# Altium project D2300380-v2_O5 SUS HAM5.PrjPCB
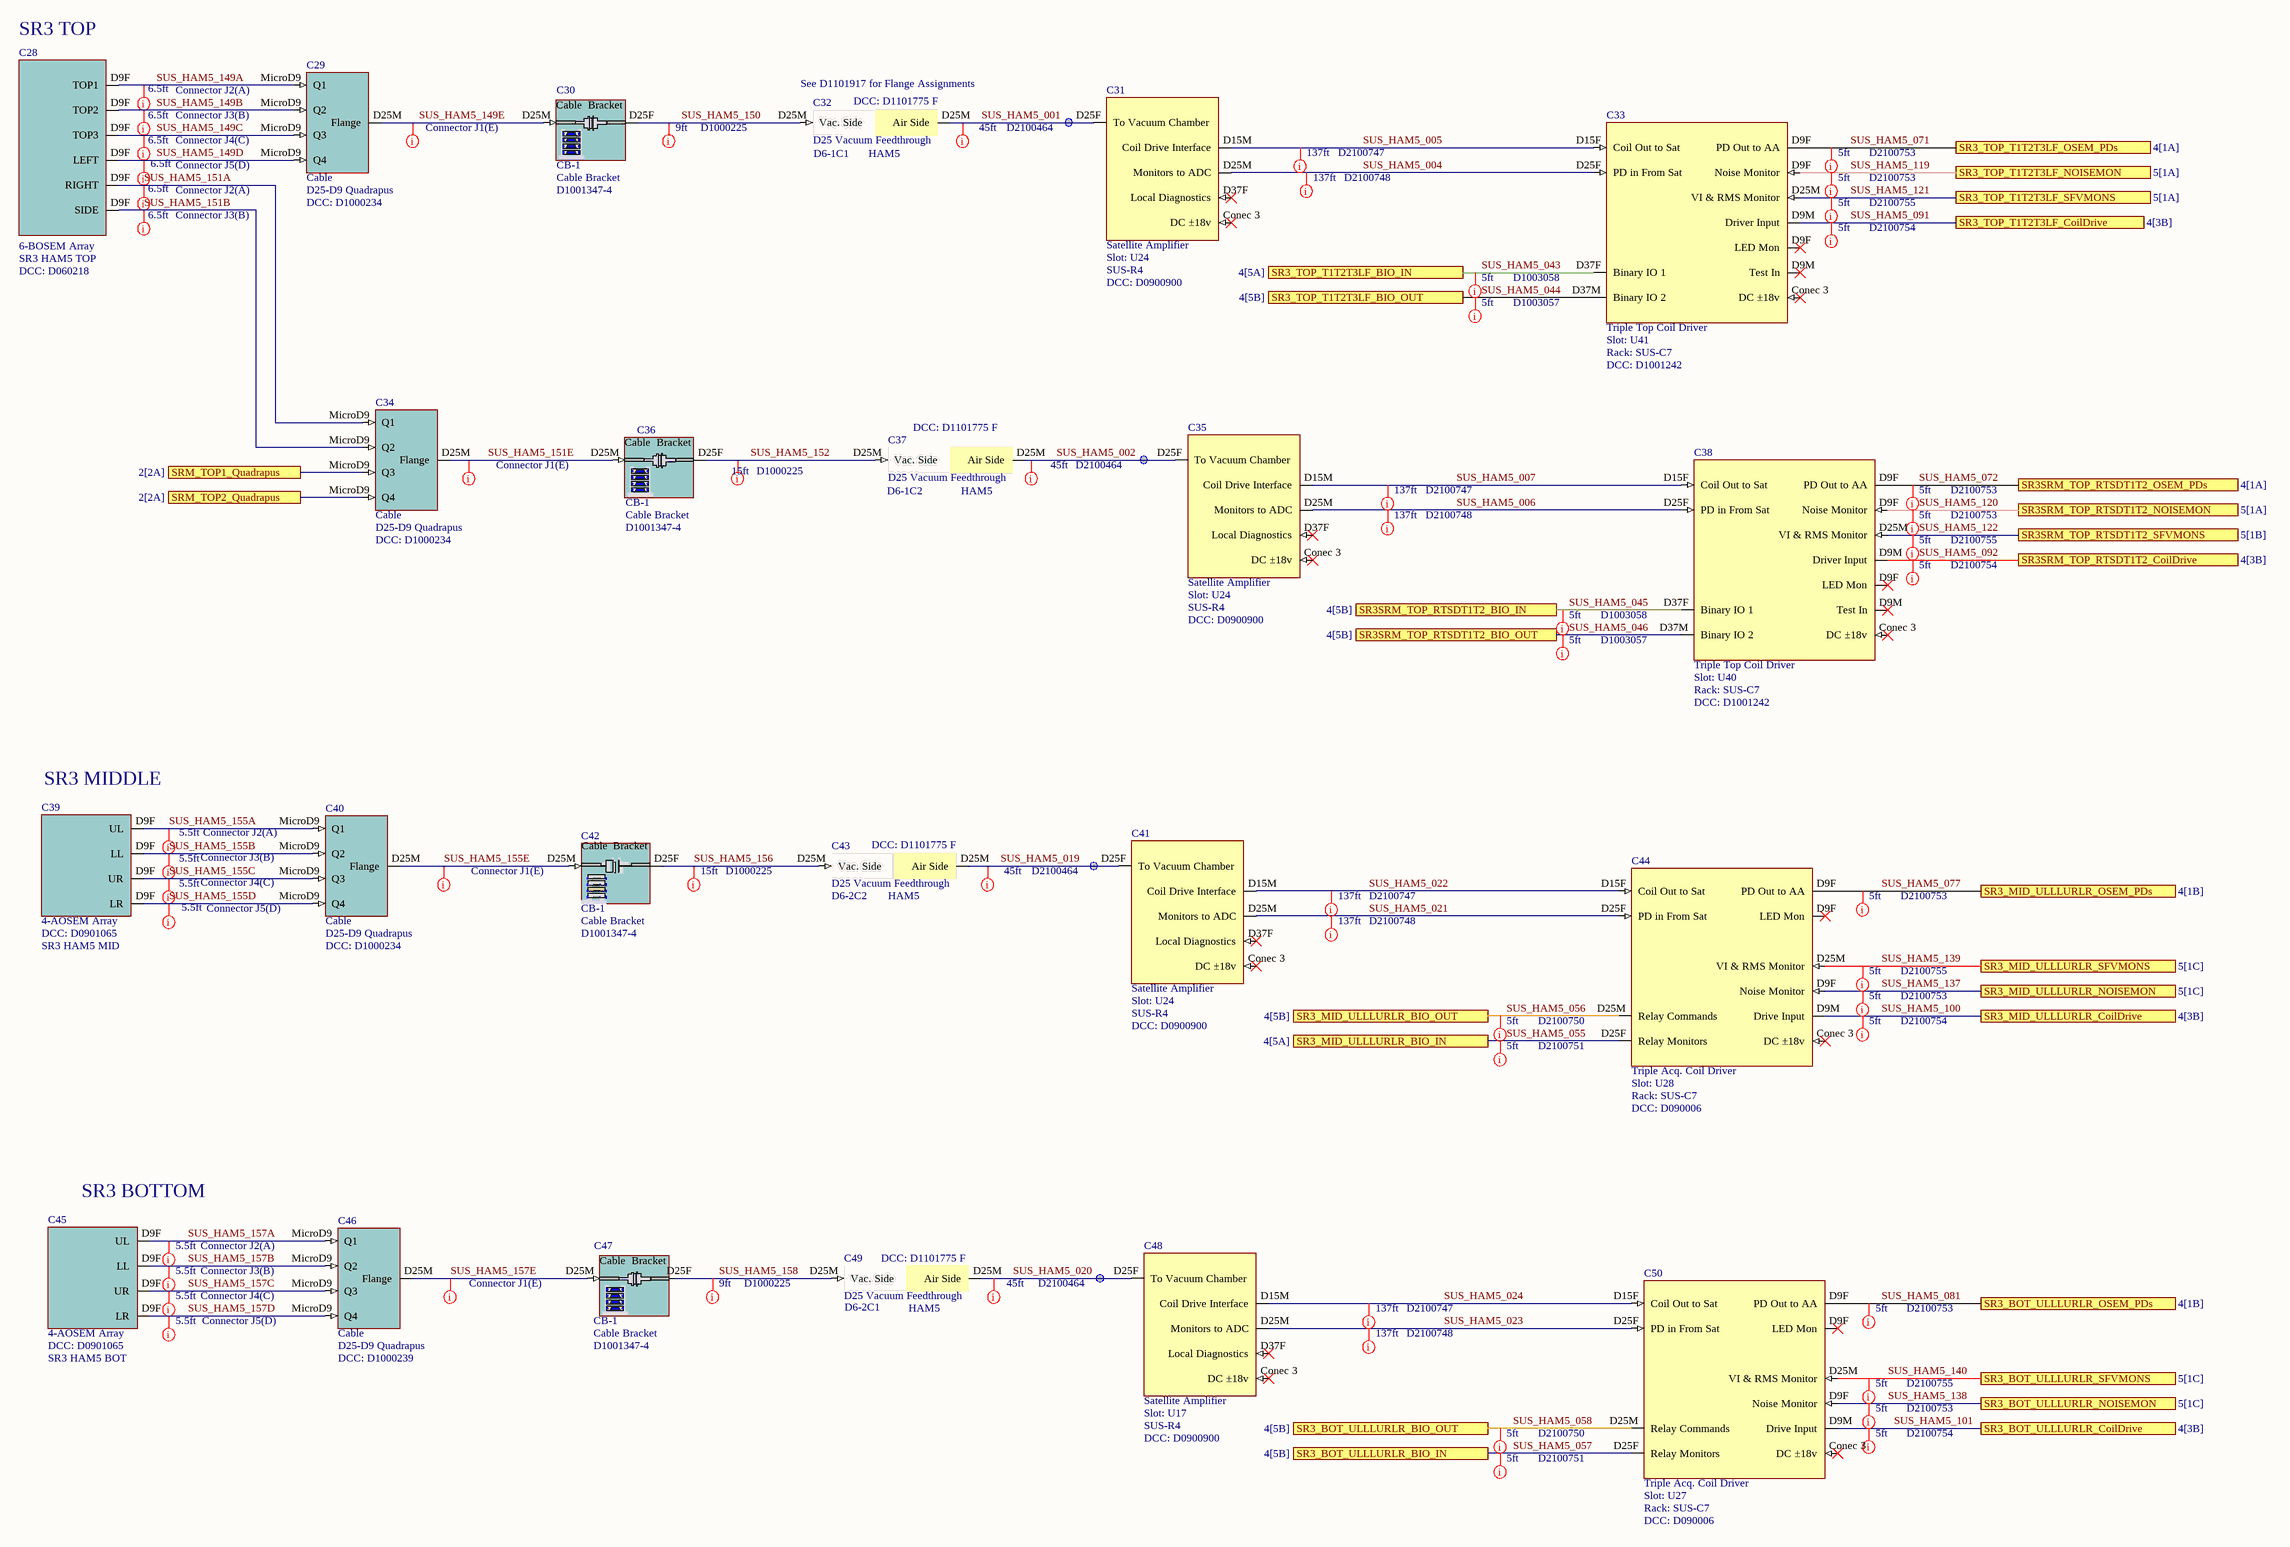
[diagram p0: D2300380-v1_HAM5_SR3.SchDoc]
7 sheets, 104 parts. Net scope: flat (ports and power ports of the same name join across sheets).
Sheets:
  D2300380-v1_HAM5_SR3.SchDoc
  D2300380-v1_HAM5_SRM.SchDoc
  D2300380-v2_HAM5_OFI_ZM6_LO3.SchDoc
  D2300380-v1_SUSH56_ADC_DAC.SchDoc
  D2300380-v1_SUSAUXH56_ADC_DAC.SchDoc
  D2300380-v1_RACK_SUS_R4.SchDoc
  D2300380-v2_RACK_SUS_C7_C8.SchDoc

## Sheet D2300380-v1_HAM5_SR3.SchDoc: HAM5 SR3 OSEMs to Drivers
size C; Engineer: L. Sanchez; Organization: LIGO Laboratory; Address1: California Institute of Technology; Address2: Massachusetts Institute of Technology; DocumentNumber: D2300380; Revision: v1; SheetNumber: 1; SheetTotal: 7

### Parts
C28  6-BOSEM Array  Parameter 1: SR3 HAM5 TOP  DCC: D060218
C29  Cable  value D25-D9 Quadrapus  DCC: D1000234
C30  Slot: CB-1  DCC: D1001347-4  (hidden comment: Cable Bracket)
C31  Satellite Amplifier  Slot: U24  Rack: SUS-R4  DCC: D0900900
C32  D25 Vacuum Feedthrough  DCC: D1101775 F  Feedthrough: D6-1C1  Chamber: HAM5
C33  Triple Top Coil Driver  Slot: U41  Rack: SUS-C7  DCC: D1001242
C34  Cable  value D25-D9 Quadrapus  DCC: D1000234
C35  Satellite Amplifier  Slot: U24  Rack: SUS-R4  DCC: D0900900
C36  Slot: CB-1  DCC: D1001347-4  (hidden comment: Cable Bracket)
C37  D25 Vacuum Feedthrough  DCC: D1101775 F  Feedthrough: D6-1C2  Chamber: HAM5
C38  Triple Top Coil Driver  Slot: U40  Rack: SUS-C7  DCC: D1001242
C39  4-AOSEM Array  DCC: D0901065  Parameter: SR3 HAM5 MID
C40  Cable  value D25-D9 Quadrapus  DCC: D1000234
C41  Satellite Amplifier  Slot: U24  Rack: SUS-R4  DCC: D0900900
C42  Slot: CB-1  DCC: D1001347-4  (hidden comment: Cable Bracket)
C43  D25 Vacuum Feedthrough  DCC: D1101775 F  Feedthrough: D6-2C2  Chamber: HAM5
C44  Triple Acq. Coil Driver  Slot: U28  Rack: SUS-C7  DCC: D090006
C45  4-AOSEM Array  DCC: D0901065  Parameter: SR3 HAM5 BOT
C46  Cable  value D25-D9 Quadrapus  DCC: D1000239
C47  Slot: CB-1  DCC: D1001347-4  (hidden comment: Cable Bracket)
C48  Satellite Amplifier  Slot: U17  Rack: SUS-R4  DCC: D0900900
C49  D25 Vacuum Feedthrough  DCC: D1101775 F  Feedthrough: D6-2C1  Chamber: HAM5
C50  Triple Acq. Coil Driver  Slot: U27  Rack: SUS-C7  DCC: D090006

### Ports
SR3_BOT_ULLLURLR_BIO_IN (see 4[5B]), SR3_BOT_ULLLURLR_BIO_OUT (see 4[5B]), SR3_BOT_ULLLURLR_CoilDrive (see 4[3B]), SR3_BOT_ULLLURLR_NOISEMON (see 5[1C]), SR3_BOT_ULLLURLR_OSEM_PDs (see 4[1B]), SR3_BOT_ULLLURLR_SFVMONS (see 5[1C]), SR3_MID_ULLLURLR_BIO_IN (see 4[5A]), SR3_MID_ULLLURLR_BIO_OUT (see 4[5B]), SR3_MID_ULLLURLR_CoilDrive (see 4[3B]), SR3_MID_ULLLURLR_NOISEMON (see 5[1C]), SR3_MID_ULLLURLR_OSEM_PDs (see 4[1B]), SR3_MID_ULLLURLR_SFVMONS (see 5[1C]), SR3_TOP_T1T2T3LF_BIO_IN (see 4[5A]), SR3_TOP_T1T2T3LF_BIO_OUT (see 4[5B]), SR3_TOP_T1T2T3LF_CoilDrive (see 4[3B]), SR3_TOP_T1T2T3LF_NOISEMON (see 5[1A]), SR3_TOP_T1T2T3LF_OSEM_PDs (see 4[1A]), SR3_TOP_T1T2T3LF_SFVMONS (see 5[1A]), SR3SRM_TOP_RTSDT1T2_BIO_IN (see 4[5B]), SR3SRM_TOP_RTSDT1T2_BIO_OUT (see 4[5B]), SR3SRM_TOP_RTSDT1T2_CoilDrive (see 4[3B]), SR3SRM_TOP_RTSDT1T2_NOISEMON (see 5[1A]), SR3SRM_TOP_RTSDT1T2_OSEM_PDs (see 4[1A]), SR3SRM_TOP_RTSDT1T2_SFVMONS (see 5[1B]), SRM_TOP1_Quadrapus (see 2[2A]), SRM_TOP2_Quadrapus (see 2[2A])

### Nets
SUS_HAM5_001: C31.D25F(To_Vacuum_Chamber) C32.D25M(Air_Side)
SUS_HAM5_002: C35.D25F(To_Vacuum_Chamber) C37.D25M(Air_Side)
SUS_HAM5_004: C31.D25M(Monitors_to_ADC) C33.D25F(PD_in_From_Sat)
SUS_HAM5_005: C31.D15M(Coil_Drive_Interface) C33.D15F(Coil_Out_to_Sat)
SUS_HAM5_006: C35.D25M(Monitors_to_ADC) C38.D25F(PD_in_From_Sat)
SUS_HAM5_007: C35.D15M(Coil_Drive_Interface) C38.D15F(Coil_Out_to_Sat)
SUS_HAM5_019: C41.D25F(To_Vacuum_Chamber) C43.D25M(Air_Side)
SUS_HAM5_020: C48.D25F(To_Vacuum_Chamber) C49.D25M(Air_Side)
SUS_HAM5_021: C41.D25M(Monitors_to_ADC) C44.D25F(PD_in_From_Sat)
SUS_HAM5_022: C41.D15M(Coil_Drive_Interface) C44.D15F(Coil_Out_to_Sat)
SUS_HAM5_023: C48.D25M(Monitors_to_ADC) C50.D25F(PD_in_From_Sat)
SUS_HAM5_024: C48.D15M(Coil_Drive_Interface) C50.D15F(Coil_Out_to_Sat)
SUS_HAM5_043: C33.D37F(Binary_IO_1) ; port SR3_TOP_T1T2T3LF_BIO_IN
SUS_HAM5_044: C33.D37M(Binary_IO_2) ; port SR3_TOP_T1T2T3LF_BIO_OUT
SUS_HAM5_045: C38.D37F(Binary_IO_1) ; port SR3SRM_TOP_RTSDT1T2_BIO_IN
SUS_HAM5_046: C38.D37M(Binary_IO_2) ; port SR3SRM_TOP_RTSDT1T2_BIO_OUT
SUS_HAM5_055: C44.D25F(Relay_Monitors) ; port SR3_MID_ULLLURLR_BIO_IN
SUS_HAM5_056: C44.D25M(Relay_Commands) ; port SR3_MID_ULLLURLR_BIO_OUT
SUS_HAM5_057: C50.D25F(Relay_Monitors) ; port SR3_BOT_ULLLURLR_BIO_IN
SUS_HAM5_058: C50.D25M(Relay_Commands) ; port SR3_BOT_ULLLURLR_BIO_OUT
SUS_HAM5_071: C33.D9F(PD_Out_to_AA) ; port SR3_TOP_T1T2T3LF_OSEM_PDs
SUS_HAM5_072: C38.D9F(PD_Out_to_AA) ; port SR3SRM_TOP_RTSDT1T2_OSEM_PDs
SUS_HAM5_077: C44.D9F(PD_Out_to_AA) ; port SR3_MID_ULLLURLR_OSEM_PDs
SUS_HAM5_081: C50.D9F(PD_Out_to_AA) ; port SR3_BOT_ULLLURLR_OSEM_PDs
SUS_HAM5_091: C33.D9M(Test_In) ; port SR3_TOP_T1T2T3LF_CoilDrive
SUS_HAM5_092: C38.D9M(Test_In) ; port SR3SRM_TOP_RTSDT1T2_CoilDrive
SUS_HAM5_100: C44.D9M(Drive_Input) ; port SR3_MID_ULLLURLR_CoilDrive
SUS_HAM5_101: C50.D9M(Drive_Input) ; port SR3_BOT_ULLLURLR_CoilDrive
SUS_HAM5_119: C33.D9F(Noise_Monitor) ; port SR3_TOP_T1T2T3LF_NOISEMON
SUS_HAM5_120: C38.D9F(Noise_Monitor) ; port SR3SRM_TOP_RTSDT1T2_NOISEMON
SUS_HAM5_121: C33.D25M(VI_&_RMS_Monitor) ; port SR3_TOP_T1T2T3LF_SFVMONS
SUS_HAM5_122: C38.D25M(VI_&_RMS_Monitor) ; port SR3SRM_TOP_RTSDT1T2_SFVMONS
SUS_HAM5_137: C44.D9F(Noise_Monitor) ; port SR3_MID_ULLLURLR_NOISEMON
SUS_HAM5_138: C50.D9F(Noise_Monitor) ; port SR3_BOT_ULLLURLR_NOISEMON
SUS_HAM5_139: C44.D25M(VI_&_RMS_Monitor) ; port SR3_MID_ULLLURLR_SFVMONS
SUS_HAM5_140: C50.D25M(VI_&_RMS_Monitor) ; port SR3_BOT_ULLLURLR_SFVMONS
SUS_HAM5_149A: C28.D9F(TOP1) C29.MicroD9(Q1)
SUS_HAM5_149B: C28.D9F(TOP2) C29.MicroD9(Q2)
SUS_HAM5_149C: C28.D9F(TOP3) C29.MicroD9(Q3)
SUS_HAM5_149D: C28.D9F(LEFT) C29.MicroD9(Q4)
SUS_HAM5_149E: C29.D25M(Flange) C30.D25M
SUS_HAM5_150: C30.D25F C32.D25M(Vac._Side)
SUS_HAM5_151A: C28.D9F(RIGHT) C34.MicroD9(Q1)
SUS_HAM5_151B: C28.D9F(SIDE) C34.MicroD9(Q2)
SUS_HAM5_151C: C34.MicroD9(Q3) ; port SRM_TOP1_Quadrapus
SUS_HAM5_151D: C34.MicroD9(Q4) ; port SRM_TOP2_Quadrapus
SUS_HAM5_151E: C34.D25M(Flange) C36.D25M
SUS_HAM5_152: C36.D25F C37.D25M(Vac._Side)
SUS_HAM5_155A: C39.D9F(UL) C40.MicroD9(Q1)
SUS_HAM5_155B: C39.D9F(LL) C40.MicroD9(Q2)
SUS_HAM5_155C: C39.D9F(UR) C40.MicroD9(Q3)
SUS_HAM5_155D: C39.D9F(LR) C40.MicroD9(Q4)
SUS_HAM5_155E: C40.D25M(Flange) C42.D25M
SUS_HAM5_156: C42.D25F C43.D25M(Vac._Side)
SUS_HAM5_157A: C45.D9F(UL) C46.MicroD9(Q1)
SUS_HAM5_157B: C45.D9F(LL) C46.MicroD9(Q2)
SUS_HAM5_157C: C45.D9F(UR) C46.MicroD9(Q3)
SUS_HAM5_157D: C45.D9F(LR) C46.MicroD9(Q4)
SUS_HAM5_157E: C46.D25M(Flange) C47.D25M
SUS_HAM5_158: C47.D25F C49.D25M(Vac._Side)

Not connected (* = marked no-connect by the designer): C31 Conec 3(DC_±18v)* D37F(Local_Diagnostics)*; C33 Conec 3(DC_±18v)*; C35 Conec 3(DC_±18v)* D37F(Local_Diagnostics)*; C38 Conec 3(DC_±18v)*; C41 Conec 3(DC_±18v)* D37F(Local_Diagnostics)*; C44 Conec 3(DC_±18v)*; C48 Conec 3(DC_±18v)* D37F(Local_Diagnostics)*; C50 Conec 3(DC_±18v)*

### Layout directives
Length: 6.5ft; DCC: Connector J1(E): SUS_HAM5_149E, SUS_HAM5_151E
Length: 15ft; DCC: D1000225: SUS_HAM5_152, SUS_HAM5_156
Length: 45ft; DCC: D2100464: SUS_HAM5_001, SUS_HAM5_002, SUS_HAM5_019, SUS_HAM5_020
Length: 6.5ft; DCC: Connector J2(A): SUS_HAM5_149A, SUS_HAM5_151A
Length: 6.5ft; DCC: Connector J3(B): SUS_HAM5_149B, SUS_HAM5_151B
Length: 9ft; DCC: D1000225: SUS_HAM5_150, SUS_HAM5_158
Length: 6.5ft; DCC: Connector J4(C): SUS_HAM5_149C
Length: 6.5ft; DCC: Connector J5(D): SUS_HAM5_149D
Length: 5ft; DCC: Connector J1(E): SUS_HAM5_157E
Length: 5.5ft; DCC: Connector J1(E): SUS_HAM5_155E
Length: 5.5ft; DCC: Connector J2(A): SUS_HAM5_155A, SUS_HAM5_157A
Length: 5.5ft; DCC: Connector J3(B): SUS_HAM5_155B, SUS_HAM5_157B
Length: 5.5ft; DCC: Connector J4(C): SUS_HAM5_155C, SUS_HAM5_157C
Length: 5.5ft; DCC: Connector J5(D): SUS_HAM5_155D, SUS_HAM5_157D
Length: 137ft; DCC: D2100748: SUS_HAM5_004, SUS_HAM5_006, SUS_HAM5_021, SUS_HAM5_023
Length: 137ft; DCC: D2100747: SUS_HAM5_005, SUS_HAM5_007, SUS_HAM5_022, SUS_HAM5_024
Length: 5ft; DCC: D1003058: SUS_HAM5_043, SUS_HAM5_045
Length: 5ft; DCC: D1003057: SUS_HAM5_044, SUS_HAM5_046
Length: 5ft; DCC: D2100754: SUS_HAM5_091, SUS_HAM5_092, SUS_HAM5_100, SUS_HAM5_101
Length: 5ft; DCC: D2100755: SUS_HAM5_121, SUS_HAM5_122, SUS_HAM5_139, SUS_HAM5_140
Length: 5ft; DCC: D2100753: SUS_HAM5_071, SUS_HAM5_072, SUS_HAM5_077, SUS_HAM5_081, SUS_HAM5_119, SUS_HAM5_120, SUS_HAM5_137, SUS_HAM5_138
Length: 5ft; DCC: D2100751: SUS_HAM5_055, SUS_HAM5_057
Length: 5ft; DCC: D2100750: SUS_HAM5_056, SUS_HAM5_058

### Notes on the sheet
- (near C28) SR3 TOP
- (near C32) See D1101917 for Flange Assignments
- (near C39) SR3 MIDDLE
- (near C45) SR3 BOTTOM

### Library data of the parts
C28 = 6-BOSEM Array HAM: Serial: Sxxxxxxx; System: SUS; Slot: U?; Rack: SUS-R?
C29 C34 C40 C46 = Flange: Rack: SUS-R?; Serial: Sxxxxxxx; Slot: U?; System: SUS
C30 = Cable Bracket 3 1-4: Rack: SUS-R?; Serial: Sxxxxxxx; System: SUS
C31 C35 C41 C48 = Satellite Amplifier: System: SUS; Serial: Sxxxxxxx
C32 C37 C43 C49 = VacFeedD25: Serial: Sxxxxxxx; System: ISC; Rack: R?; Slot: U?
C33 C38 = Triple Top CD: System: SUS; Serial: Sxxxxxxx
C36 = Cable Bracket 4 1-4: Rack: SUS-R?; Serial: Sxxxxxxx; System: SUS
C39 C45 = 4-BOSEM Array: Rack: SUS-R?; Serial: Sxxxxxxx; Slot: U?; System: SUS
C42 = Cable Bracket 2 1-4: Rack: SUS-R?; Serial: Sxxxxxxx; System: SUS
C44 C50 = Triple Acquisition Coil Driver: System: SUS; Serial: Sxxxxxxx
C47 = Cable Bracket 1 1-4: Rack: SUS-R?; Serial: Sxxxxxxx; System: SUS

## Sheet D2300380-v1_HAM5_SRM.SchDoc: HAM5 SRM OSEMs to Drivers
size C; Engineer: L. Sanchez; Organization: LIGO Laboratory; Address1: California Institute of Technology; Address2: Massachusetts Institute of Technology; DocumentNumber: D2300380; Revision: v1; SheetNumber: 2; SheetTotal: 7
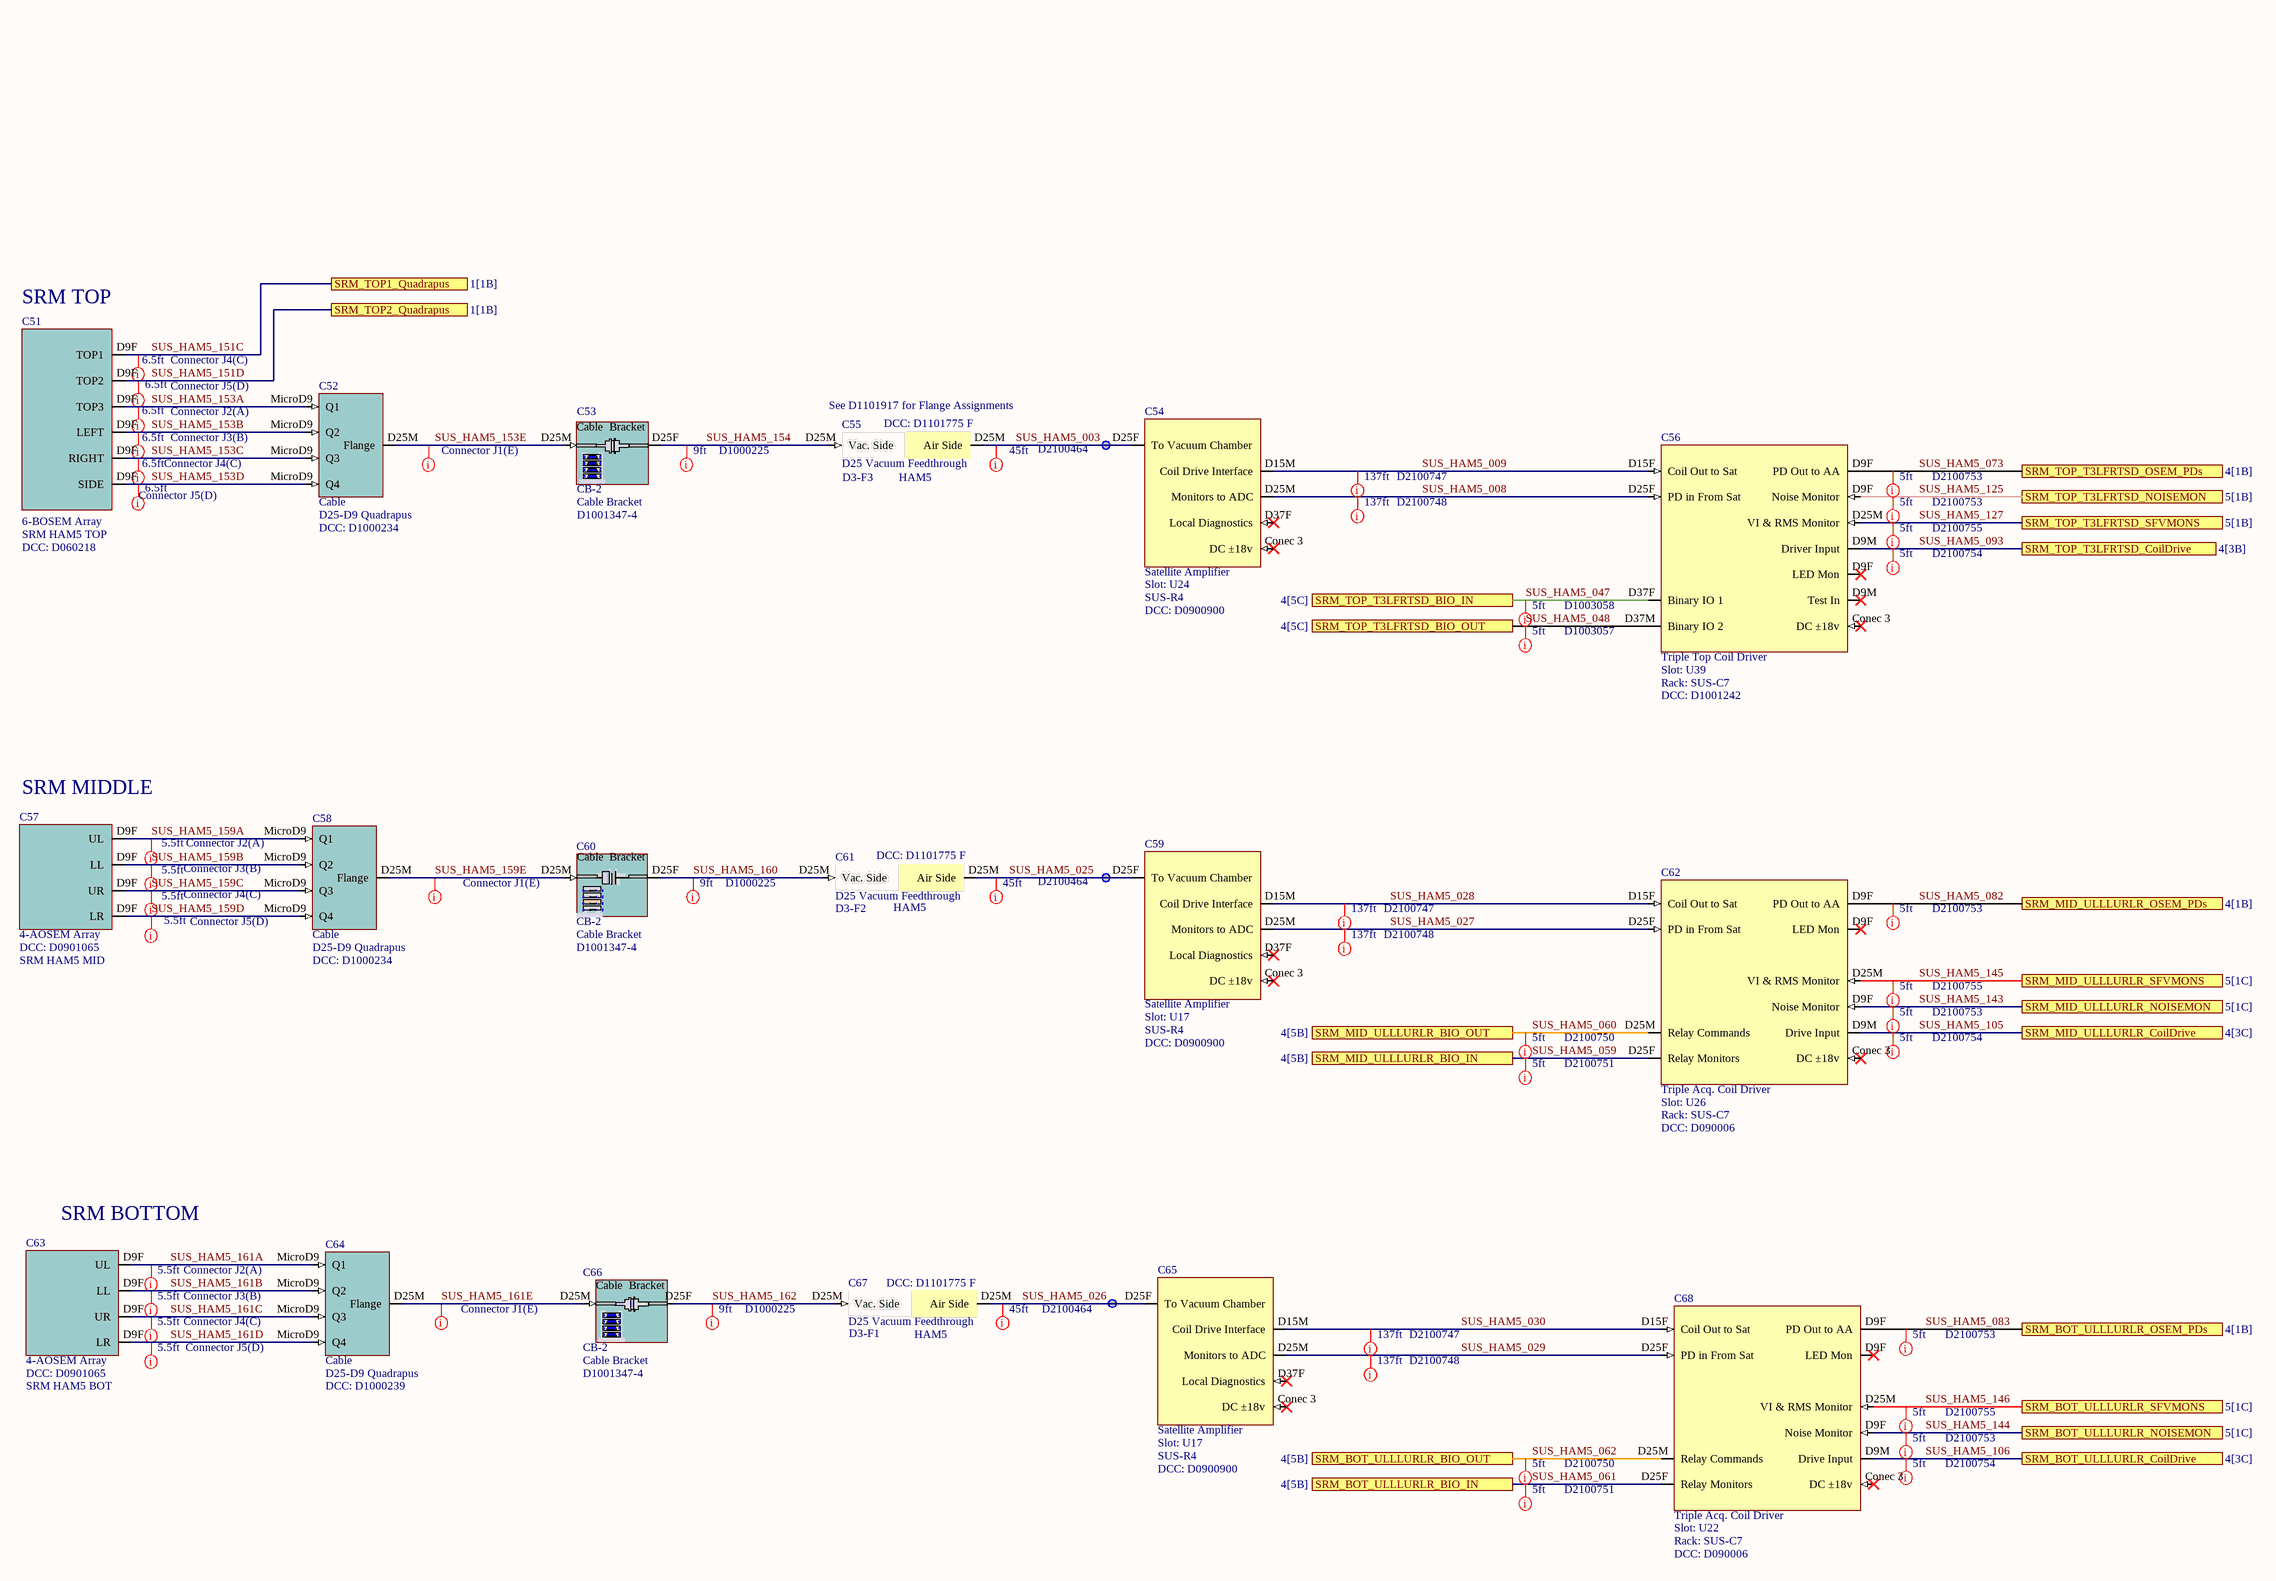
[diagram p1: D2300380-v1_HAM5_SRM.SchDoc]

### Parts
C51  6-BOSEM Array  Parameter 1: SRM HAM5 TOP  DCC: D060218
C52  Cable  value D25-D9 Quadrapus  DCC: D1000234
C53  Slot: CB-2  DCC: D1001347-4  (hidden comment: Cable Bracket)
C54  Satellite Amplifier  Slot: U24  Rack: SUS-R4  DCC: D0900900
C55  D25 Vacuum Feedthrough  DCC: D1101775 F  Feedthrough: D3-F3  Chamber: HAM5
C56  Triple Top Coil Driver  Slot: U39  Rack: SUS-C7  DCC: D1001242
C57  4-AOSEM Array  DCC: D0901065  Parameter: SRM HAM5 MID
C58  Cable  value D25-D9 Quadrapus  DCC: D1000234
C59  Satellite Amplifier  Slot: U17  Rack: SUS-R4  DCC: D0900900
C60  Slot: CB-2  DCC: D1001347-4  (hidden comment: Cable Bracket)
C61  D25 Vacuum Feedthrough  DCC: D1101775 F  Feedthrough: D3-F2  Chamber: HAM5
C62  Triple Acq. Coil Driver  Slot: U26  Rack: SUS-C7  DCC: D090006
C63  4-AOSEM Array  DCC: D0901065  Parameter: SRM HAM5 BOT
C64  Cable  value D25-D9 Quadrapus  DCC: D1000239
C65  Satellite Amplifier  Slot: U17  Rack: SUS-R4  DCC: D0900900
C66  Slot: CB-2  DCC: D1001347-4  (hidden comment: Cable Bracket)
C67  D25 Vacuum Feedthrough  DCC: D1101775 F  Feedthrough: D3-F1  Chamber: HAM5
C68  Triple Acq. Coil Driver  Slot: U22  Rack: SUS-C7  DCC: D090006

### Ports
SRM_BOT_ULLLURLR_BIO_IN (see 4[5B]), SRM_BOT_ULLLURLR_BIO_OUT (see 4[5B]), SRM_BOT_ULLLURLR_CoilDrive (see 4[3C]), SRM_BOT_ULLLURLR_NOISEMON (see 5[1C]), SRM_BOT_ULLLURLR_OSEM_PDs (see 4[1B]), SRM_BOT_ULLLURLR_SFVMONS (see 5[1C]), SRM_MID_ULLLURLR_BIO_IN (see 4[5B]), SRM_MID_ULLLURLR_BIO_OUT (see 4[5B]), SRM_MID_ULLLURLR_CoilDrive (see 4[3C]), SRM_MID_ULLLURLR_NOISEMON (see 5[1C]), SRM_MID_ULLLURLR_OSEM_PDs (see 4[1B]), SRM_MID_ULLLURLR_SFVMONS (see 5[1C]), SRM_TOP1_Quadrapus (see 1[1B]), SRM_TOP2_Quadrapus (see 1[1B]), SRM_TOP_T3LFRTSD_BIO_IN (see 4[5C]), SRM_TOP_T3LFRTSD_BIO_OUT (see 4[5C]), SRM_TOP_T3LFRTSD_CoilDrive (see 4[3B]), SRM_TOP_T3LFRTSD_NOISEMON (see 5[1B]), SRM_TOP_T3LFRTSD_OSEM_PDs (see 4[1B]), SRM_TOP_T3LFRTSD_SFVMONS (see 5[1B])

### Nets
SUS_HAM5_003: C54.D25F(To_Vacuum_Chamber) C55.D25M(Air_Side)
SUS_HAM5_008: C54.D25M(Monitors_to_ADC) C56.D25F(PD_in_From_Sat)
SUS_HAM5_009: C54.D15M(Coil_Drive_Interface) C56.D15F(Coil_Out_to_Sat)
SUS_HAM5_025: C59.D25F(To_Vacuum_Chamber) C61.D25M(Air_Side)
SUS_HAM5_026: C65.D25F(To_Vacuum_Chamber) C67.D25M(Air_Side)
SUS_HAM5_027: C59.D25M(Monitors_to_ADC) C62.D25F(PD_in_From_Sat)
SUS_HAM5_028: C59.D15M(Coil_Drive_Interface) C62.D15F(Coil_Out_to_Sat)
SUS_HAM5_029: C65.D25M(Monitors_to_ADC) C68.D25F(PD_in_From_Sat)
SUS_HAM5_030: C65.D15M(Coil_Drive_Interface) C68.D15F(Coil_Out_to_Sat)
SUS_HAM5_047: C56.D37F(Binary_IO_1) ; port SRM_TOP_T3LFRTSD_BIO_IN
SUS_HAM5_048: C56.D37M(Binary_IO_2) ; port SRM_TOP_T3LFRTSD_BIO_OUT
SUS_HAM5_059: C62.D25F(Relay_Monitors) ; port SRM_MID_ULLLURLR_BIO_IN
SUS_HAM5_060: C62.D25M(Relay_Commands) ; port SRM_MID_ULLLURLR_BIO_OUT
SUS_HAM5_061: C68.D25F(Relay_Monitors) ; port SRM_BOT_ULLLURLR_BIO_IN
SUS_HAM5_062: C68.D25M(Relay_Commands) ; port SRM_BOT_ULLLURLR_BIO_OUT
SUS_HAM5_073: C56.D9F(PD_Out_to_AA) ; port SRM_TOP_T3LFRTSD_OSEM_PDs
SUS_HAM5_082: C62.D9F(PD_Out_to_AA) ; port SRM_MID_ULLLURLR_OSEM_PDs
SUS_HAM5_083: C68.D9F(PD_Out_to_AA) ; port SRM_BOT_ULLLURLR_OSEM_PDs
SUS_HAM5_093: C56.D9M(Test_In) ; port SRM_TOP_T3LFRTSD_CoilDrive
SUS_HAM5_105: C62.D9M(Drive_Input) ; port SRM_MID_ULLLURLR_CoilDrive
SUS_HAM5_106: C68.D9M(Drive_Input) ; port SRM_BOT_ULLLURLR_CoilDrive
SUS_HAM5_125: C56.D9F(Noise_Monitor) ; port SRM_TOP_T3LFRTSD_NOISEMON
SUS_HAM5_127: C56.D25M(VI_&_RMS_Monitor) ; port SRM_TOP_T3LFRTSD_SFVMONS
SUS_HAM5_143: C62.D9F(Noise_Monitor) ; port SRM_MID_ULLLURLR_NOISEMON
SUS_HAM5_144: C68.D9F(Noise_Monitor) ; port SRM_BOT_ULLLURLR_NOISEMON
SUS_HAM5_145: C62.D25M(VI_&_RMS_Monitor) ; port SRM_MID_ULLLURLR_SFVMONS
SUS_HAM5_146: C68.D25M(VI_&_RMS_Monitor) ; port SRM_BOT_ULLLURLR_SFVMONS
SUS_HAM5_151C: C51.D9F(TOP1) ; port SRM_TOP1_Quadrapus
SUS_HAM5_151D: C51.D9F(TOP2) ; port SRM_TOP2_Quadrapus
SUS_HAM5_153A: C51.D9F(TOP3) C52.MicroD9(Q1)
SUS_HAM5_153B: C51.D9F(LEFT) C52.MicroD9(Q2)
SUS_HAM5_153C: C51.D9F(RIGHT) C52.MicroD9(Q3)
SUS_HAM5_153D: C51.D9F(SIDE) C52.MicroD9(Q4)
SUS_HAM5_153E: C52.D25M(Flange) C53.D25M
SUS_HAM5_154: C53.D25F C55.D25M(Vac._Side)
SUS_HAM5_159A: C57.D9F(UL) C58.MicroD9(Q1)
SUS_HAM5_159B: C57.D9F(LL) C58.MicroD9(Q2)
SUS_HAM5_159C: C57.D9F(UR) C58.MicroD9(Q3)
SUS_HAM5_159D: C57.D9F(LR) C58.MicroD9(Q4)
SUS_HAM5_159E: C58.D25M(Flange) C60.D25M
SUS_HAM5_160: C60.D25F C61.D25M(Vac._Side)
SUS_HAM5_161A: C63.D9F(UL) C64.MicroD9(Q1)
SUS_HAM5_161B: C63.D9F(LL) C64.MicroD9(Q2)
SUS_HAM5_161C: C63.D9F(UR) C64.MicroD9(Q3)
SUS_HAM5_161D: C63.D9F(LR) C64.MicroD9(Q4)
SUS_HAM5_161E: C64.D25M(Flange) C66.D25M
SUS_HAM5_162: C66.D25F C67.D25M(Vac._Side)

Not connected (* = marked no-connect by the designer): C54 Conec 3(DC_±18v)* D37F(Local_Diagnostics)*; C56 Conec 3(DC_±18v)*; C59 Conec 3(DC_±18v)* D37F(Local_Diagnostics)*; C62 Conec 3(DC_±18v)*; C65 Conec 3(DC_±18v)* D37F(Local_Diagnostics)*; C68 Conec 3(DC_±18v)*

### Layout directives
Length: 5ft; DCC: Connector J1(E): SUS_HAM5_161E
Length: 5.5ft; DCC: Connector J1(E): SUS_HAM5_159E
Length: 6.5ft; DCC: Connector J1(E): SUS_HAM5_153E
Length: 6.5ft; DCC: Connector J2(A): SUS_HAM5_153A
Length: 6.5ft; DCC: Connector J3(B): SUS_HAM5_153B
Length: 6.5ft; DCC: Connector J4(C): SUS_HAM5_151C, SUS_HAM5_153C
Length: 6.5ft; DCC: Connector J5(D): SUS_HAM5_151D, SUS_HAM5_153D
Length: 5.5ft; DCC: Connector J2(A): SUS_HAM5_159A, SUS_HAM5_161A
Length: 5.5ft; DCC: Connector J3(B): SUS_HAM5_159B, SUS_HAM5_161B
Length: 5.5ft; DCC: Connector J4(C): SUS_HAM5_159C, SUS_HAM5_161C
Length: 5.5ft; DCC: Connector J5(D): SUS_HAM5_159D, SUS_HAM5_161D
Length: 9ft; DCC: D1000225: SUS_HAM5_154, SUS_HAM5_160, SUS_HAM5_162
Length: 45ft; DCC: D2100464: SUS_HAM5_003, SUS_HAM5_025, SUS_HAM5_026
Length: 137ft; DCC: D2100748: SUS_HAM5_008, SUS_HAM5_027, SUS_HAM5_029
Length: 137ft; DCC: D2100747: SUS_HAM5_009, SUS_HAM5_028, SUS_HAM5_030
Length: 5ft; DCC: D1003057: SUS_HAM5_048
Length: 5ft; DCC: D1003058: SUS_HAM5_047
Length: 5ft; DCC: D2100751: SUS_HAM5_059, SUS_HAM5_061
Length: 5ft; DCC: D2100750: SUS_HAM5_060, SUS_HAM5_062
Length: 5ft; DCC: D2100754: SUS_HAM5_093, SUS_HAM5_105, SUS_HAM5_106
Length: 5ft; DCC: D2100755: SUS_HAM5_127, SUS_HAM5_145, SUS_HAM5_146
Length: 5ft; DCC: D2100753: SUS_HAM5_073, SUS_HAM5_082, SUS_HAM5_083, SUS_HAM5_125, SUS_HAM5_143, SUS_HAM5_144

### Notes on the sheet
- (near C51) SRM TOP
- (near C55) See D1101917 for Flange Assignments
- (near C57) SRM MIDDLE
- (near C63) SRM BOTTOM

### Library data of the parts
C51 = 6-BOSEM Array HAM: as C28 on sheet D2300380-v1_HAM5_SR3
C52 C58 C64 = Flange: as C29 on sheet D2300380-v1_HAM5_SR3
C53 = Cable Bracket 3 1-4: as C30 on sheet D2300380-v1_HAM5_SR3
C54 C59 C65 = Satellite Amplifier: System: SUS; Serial: Sxxxxxxx
C55 C61 C67 = VacFeedD25: as C32 on sheet D2300380-v1_HAM5_SR3
C56 = Triple Top CD: System: SUS; Serial: Sxxxxxxx
C57 C63 = 4-BOSEM Array: as C39 on sheet D2300380-v1_HAM5_SR3
C60 = Cable Bracket 2 1-4: as C42 on sheet D2300380-v1_HAM5_SR3
C62 C68 = Triple Acquisition Coil Driver: System: SUS; Serial: Sxxxxxxx
C66 = Cable Bracket 1 1-4: as C47 on sheet D2300380-v1_HAM5_SR3

## Sheet D2300380-v2_HAM5_OFI_ZM6_LO3.SchDoc: HAM5 OFI, ZM6, LO3 OSEMs to Drivers
size C; Engineer: L. Sanchez; Organization: LIGO Laboratory; Address1: California Institute of Technology; Address2: Massachusetts Institute of Technology; DocumentNumber: D2300380; Revision: v1; SheetNumber: 3; SheetTotal: 7
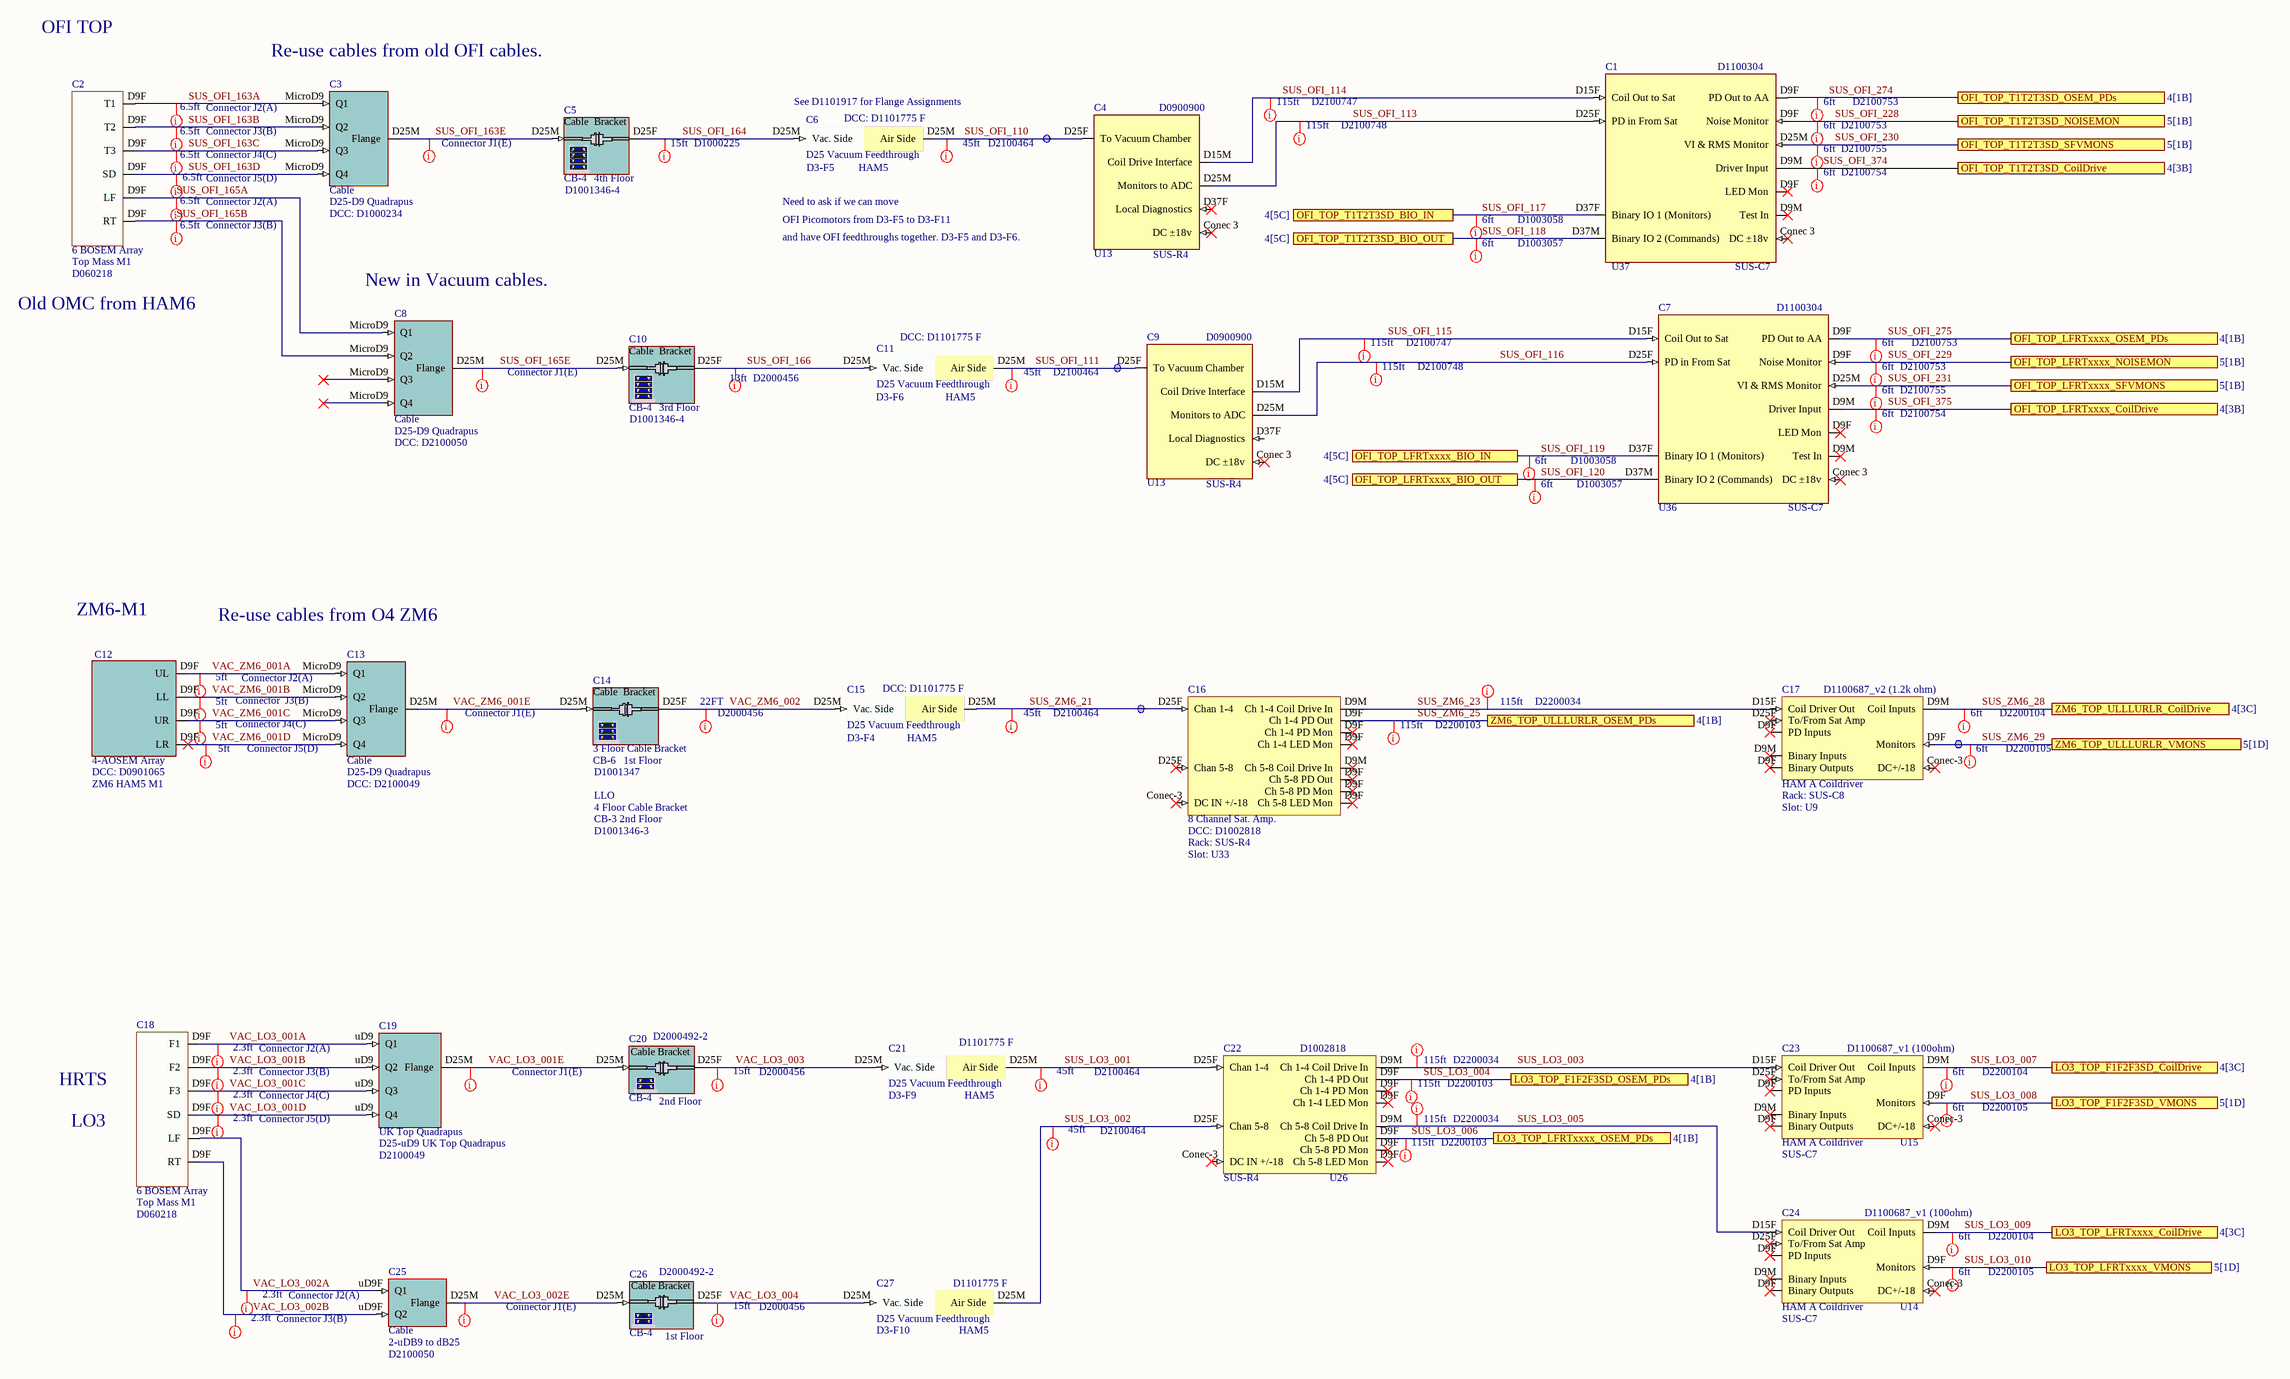
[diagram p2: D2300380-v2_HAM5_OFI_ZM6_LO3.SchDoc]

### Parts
C1  Slot: U37  Rack: SUS-C7  DCC: D1100304  (hidden comment: CD OMC TCD D1100304)
C2  6 BOSEM Array  Parameter: Top Mass M1  DCC: D060218
C3  Cable  value D25-D9 Quadrapus  DCC: D1000234
C4  Slot: U13  Rack: SUS-R4  DCC: D0900900  (hidden comment: Satellite Amplifier UK D0900900)
C5  Rack: CB-4  Slot: 4th Floor  DCC: D1001346-4  (hidden comment: D1001346-4 4th Cable Bracket)
C6  D25 Vacuum Feedthrough  DCC: D1101775 F  Feedthrough: D3-F5  Chamber: HAM5
C7  Slot: U36  Rack: SUS-C7  DCC: D1100304  (hidden comment: CD OMC TCD D1100304)
C8  Cable  value D25-D9 Quadrapus  DCC: D2100050
C9  Slot: U13  Rack: SUS-R4  DCC: D0900900  (hidden comment: Satellite Amplifier UK D0900900)
C10  Rack: CB-4  Slot: 3rd Floor  DCC: D1001346-4  (hidden comment: D1001346-4 3rd Cable Bracket)
C11  D25 Vacuum Feedthrough  DCC: D1101775 F  Feedthrough: D3-F6  Chamber: HAM5
C12  4-AOSEM Array  DCC: D0901065  Parameter: ZM6 HAM5 M1
C13  Cable  value D25-D9 Quadrapus  DCC: D2100049
C14  3 Floor Cable Bracket  Rack: CB-6  Slot: 1st Floor  DCC: D1001347
C15  D25 Vacuum Feedthrough  DCC: D1101775 F  Feedthrough: D3-F4  Chamber: HAM5
C16  8 Channel Sat. Amp.  DCC: D1002818  Rack: SUS-R4  Slot: U33
C17  HAM A Coildriver  DCC: D1100687_v2 (1.2k ohm)  Rack: SUS-C8  Slot: U9
C18  6 BOSEM Array  Parameter: Top Mass M1  DCC: D060218
C19  UK Top Quadrapus  Parameter: D25-uD9 UK Top Quadrapus  DCC: D2100049
C20  Rack: CB-4  Slot: 2nd Floor  DCC: D2000492-2  (hidden comment: Cable Bracket)
C21  D25 Vacuum Feedthrough  value D3-F9  DCC: D1101775 F  Chamber: HAM5
C22  DCC: D1002818  Rack: SUS-R4  Slot: U26  (hidden comment: Satellite Amplifier US D1002818 Dual)
C23  HAM A Coildriver  DCC: D1100687_v1 (100ohm)  Rack: SUS-C7  Slot: U15
C24  HAM A Coildriver  DCC: D1100687_v1 (100ohm)  Rack: SUS-C7  Slot: U14
C25  Cable  value 2-uDB9 to dB25  DCC: D2100050
C26  Rack: CB-4  Slot: 1st Floor  DCC: D2000492-2  (hidden comment: Cable Bracket)
C27  D25 Vacuum Feedthrough  value D3-F10  DCC: D1101775 F  Chamber: HAM5

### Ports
LO3_TOP_F1F2F3SD_CoilDrive (see 4[3C]), LO3_TOP_F1F2F3SD_OSEM_PDs (see 4[1B]), LO3_TOP_F1F2F3SD_VMONS (see 5[1D]), LO3_TOP_LFRTxxxx_CoilDrive (see 4[3C]), LO3_TOP_LFRTxxxx_OSEM_PDs (see 4[1B]), LO3_TOP_LFRTxxxx_VMONS (see 5[1D]), OFI_TOP_LFRTxxxx_BIO_IN (see 4[5C]), OFI_TOP_LFRTxxxx_BIO_OUT (see 4[5C]), OFI_TOP_LFRTxxxx_CoilDrive (see 4[3B]), OFI_TOP_LFRTxxxx_NOISEMON (see 5[1B]), OFI_TOP_LFRTxxxx_OSEM_PDs (see 4[1B]), OFI_TOP_LFRTxxxx_SFVMONS (see 5[1B]), OFI_TOP_T1T2T3SD_BIO_IN (see 4[5C]), OFI_TOP_T1T2T3SD_BIO_OUT (see 4[5C]), OFI_TOP_T1T2T3SD_CoilDrive (see 4[3B]), OFI_TOP_T1T2T3SD_NOISEMON (see 5[1B]), OFI_TOP_T1T2T3SD_OSEM_PDs (see 4[1B]), OFI_TOP_T1T2T3SD_SFVMONS (see 5[1B]), ZM6_TOP_ULLLURLR_CoilDrive (see 4[3C]), ZM6_TOP_ULLLURLR_OSEM_PDs (see 4[1B]), ZM6_TOP_ULLLURLR_VMONS (see 5[1D])

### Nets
SUS_LO3_001: C21.D25M(Air_Side) C22.D25F(Chan_1-4)
SUS_LO3_002: C22.D25F(Chan_5-8) C27.D25M(Air_Side)
SUS_LO3_003: C22.D9M(Ch_1-4_Coil_Drive_In) C23.D15F(Coil_Driver_Out)
SUS_LO3_004: C22.D9F(Ch_1-4_PD_Out) ; port LO3_TOP_F1F2F3SD_OSEM_PDs
SUS_LO3_005: C22.D9M(Ch_5-8_Coil_Drive_In) C24.D15F(Coil_Driver_Out)
SUS_LO3_006: C22.D9F(Ch_5-8_PD_Out) ; port LO3_TOP_LFRTxxxx_OSEM_PDs
SUS_LO3_007: C23.D9M(Coil_Inputs) ; port LO3_TOP_F1F2F3SD_CoilDrive
SUS_LO3_008: C23.D9F(PD_Inputs) ; port LO3_TOP_F1F2F3SD_VMONS
SUS_LO3_009: C24.D9M(Coil_Inputs) ; port LO3_TOP_LFRTxxxx_CoilDrive
SUS_LO3_010: C24.D9F(PD_Inputs) ; port LO3_TOP_LFRTxxxx_VMONS
SUS_OFI_110: C4.D25F(To_Vacuum_Chamber) C6.D25M(Air_Side)
SUS_OFI_111: C9.D25F(To_Vacuum_Chamber) C11.D25M(Air_Side)
SUS_OFI_113: C1.D25F(PD_in_From_Sat) C4.D25M(Monitors_to_ADC)
SUS_OFI_114: C1.D15F(Coil_Out_to_Sat) C4.D15M(Coil_Drive_Interface)
SUS_OFI_115: C7.D15F(Coil_Out_to_Sat) C9.D15M(Coil_Drive_Interface)
SUS_OFI_116: C7.D25F(PD_in_From_Sat) C9.D25M(Monitors_to_ADC)
SUS_OFI_117: C1.D37F(Binary_IO_1_(Monitors)) ; port OFI_TOP_T1T2T3SD_BIO_IN
SUS_OFI_118: C1.D37M(Binary_IO_2_(Commands)) ; port OFI_TOP_T1T2T3SD_BIO_OUT
SUS_OFI_119: C7.D37F(Binary_IO_1_(Monitors)) ; port OFI_TOP_LFRTxxxx_BIO_IN
SUS_OFI_120: C7.D37M(Binary_IO_2_(Commands)) ; port OFI_TOP_LFRTxxxx_BIO_OUT
SUS_OFI_163A: C2.D9F(T1) C3.MicroD9(Q1)
SUS_OFI_163B: C2.D9F(T2) C3.MicroD9(Q2)
SUS_OFI_163C: C2.D9F(T3) C3.MicroD9(Q3)
SUS_OFI_163D: C2.D9F(SD) C3.MicroD9(Q4)
SUS_OFI_163E: C3.D25M(Flange) C5.D25M
SUS_OFI_164: C5.D25F C6.D25M(Vac._Side)
SUS_OFI_165A: C2.D9F(LF) C8.MicroD9(Q1)
SUS_OFI_165B: C2.D9F(RT) C8.MicroD9(Q2)
SUS_OFI_165E: C8.D25M(Flange) C10.D25M
SUS_OFI_166: C10.D25F C11.D25M(Vac._Side)
SUS_OFI_228: C1.D9F(Noise_Monitor) ; port OFI_TOP_T1T2T3SD_NOISEMON
SUS_OFI_229: C7.D9F(Noise_Monitor) ; port OFI_TOP_LFRTxxxx_NOISEMON
SUS_OFI_230: C1.D25M(VI_&_RMS_Monitor) ; port OFI_TOP_T1T2T3SD_SFVMONS
SUS_OFI_231: C7.D25M(VI_&_RMS_Monitor) ; port OFI_TOP_LFRTxxxx_SFVMONS
SUS_OFI_274: C1.D9F(PD_Out_to_AA) ; port OFI_TOP_T1T2T3SD_OSEM_PDs
SUS_OFI_275: C7.D9F(PD_Out_to_AA) ; port OFI_TOP_LFRTxxxx_OSEM_PDs
SUS_OFI_374: C1.D9M(Test_In) ; port OFI_TOP_T1T2T3SD_CoilDrive
SUS_OFI_375: C7.D9M(Test_In) ; port OFI_TOP_LFRTxxxx_CoilDrive
SUS_ZM6_21: C15.D25M(Air_Side) C16.D25F(Chan_1-4)
SUS_ZM6_23: C16.D9M(Ch_1-4_Coil_Drive_In) C17.D15F(Coil_Driver_Out)
SUS_ZM6_25: C16.D9F(Ch_1-4_PD_Out) ; port ZM6_TOP_ULLLURLR_OSEM_PDs
SUS_ZM6_28: C17.D9M(Coil_Inputs) ; port ZM6_TOP_ULLLURLR_CoilDrive
SUS_ZM6_29: C17.D9F(PD_Inputs) ; port ZM6_TOP_ULLLURLR_VMONS
VAC_LO3_001A: C18.D9F(F1) C19.uD9(Q1)
VAC_LO3_001B: C18.D9F(F2) C19.uD9(Q2)
VAC_LO3_001C: C18.D9F(F3) C19.uD9(Q3)
VAC_LO3_001D: C18.D9F(SD) C19.uD9(Q4)
VAC_LO3_001E: C19.D25M(Flange) C20.D25M
VAC_LO3_002A: C18.D9F(LF) C25.uD9F(Q1)
VAC_LO3_002B: C18.D9F(RT) C25.uD9F(Q2)
VAC_LO3_002E: C25.D25M(Flange) C26.D25M
VAC_LO3_003: C20.D25F C21.D25M(Vac._Side)
VAC_LO3_004: C26.D25F C27.D25M(Vac._Side)
VAC_ZM6_001A: C12.D9F(UL) C13.MicroD9(Q1)
VAC_ZM6_001B: C12.D9F(LL) C13.MicroD9(Q2)
VAC_ZM6_001C: C12.D9F(UR) C13.MicroD9(Q3)
VAC_ZM6_001D: C12.D9F(LR) C13.MicroD9(Q4)
VAC_ZM6_001E: C13.D25M(Flange) C14.D25M
VAC_ZM6_002: C14.D25F C15.D25M(Vac._Side)

Not connected (* = marked no-connect by the designer): C1 Conec 3(DC_±18v)*; C4 Conec 3(DC_±18v)* D37F(Local_Diagnostics)*; C7 Conec 3(DC_±18v)*; C9 Conec 3(DC_±18v)* D37F(Local_Diagnostics); C16 Conec-3(DC_IN_+/-18)*; C17 Conec-3(DC+/-18)* D25F(To/From_Sat_Amp)*; C22 Conec-3(DC_IN_+/-18)*; C23 Conec-3(DC+/-18)* D25F(To/From_Sat_Amp)*; C24 Conec-3(DC+/-18)* D25F(To/From_Sat_Amp)*

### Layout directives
Length: 5ft; DCC: Connector J5(D): VAC_ZM6_001D
Length: 5ft; DCC: Connector J2(A): VAC_ZM6_001A
Length: 5ft; DCC: Connector  J3(B): VAC_ZM6_001B
Length: 5ft; DCC: Connector J4(C): VAC_ZM6_001C
Length: 115ft; DCC: D2200034: SUS_LO3_003, SUS_LO3_005, SUS_ZM6_23
Length: 115ft; DCC: D2200103: SUS_LO3_004, SUS_LO3_006, SUS_ZM6_25
Length: 6ft; DCC: D2200105: SUS_LO3_008, SUS_LO3_010, SUS_ZM6_29
Length: 6ft; DCC: D2200104: SUS_LO3_007, SUS_LO3_009, SUS_ZM6_28
Length: 2.3ft; DCC: Connector J2(A): VAC_LO3_001A, VAC_LO3_002A
Length: 2.3ft; DCC: Connector J3(B): VAC_LO3_001B, VAC_LO3_002B
Length: 2.3ft; DCC: Connector J4(C): VAC_LO3_001C
Length: 2.3ft; DCC: Connector J5(D): VAC_LO3_001D
Length: 2.3ft; DCC: Connector J1(E): VAC_LO3_001E, VAC_LO3_002E
Length: 15ft; DCC: D2000456: VAC_LO3_003, VAC_LO3_004
Length: 6.5ft; DCC: Connector J1(E): SUS_OFI_163E, SUS_OFI_165E
Length: 13ft; DCC: D2000456: SUS_OFI_166
Length: 45ft; DCC: D2100464: SUS_LO3_001, SUS_LO3_002, SUS_OFI_110, SUS_OFI_111, SUS_ZM6_21
Length: 6.5ft; DCC: Connector J2(A): SUS_OFI_163A, SUS_OFI_165A
Length: 6.5ft; DCC: Connector J3(B): SUS_OFI_163B, SUS_OFI_165B
Length: 15ft; DCC: D1000225: SUS_OFI_164
Length: 6.5ft; DCC: Connector J4(C): SUS_OFI_163C
Length: 6.5ft; DCC: Connector J5(D): SUS_OFI_163D
Length: 115ft; DCC: D2100747: SUS_OFI_114, SUS_OFI_115
Length: 115ft; DCC: D2100748: SUS_OFI_113, SUS_OFI_116
Length: 6ft; DCC: D2100754: SUS_OFI_374, SUS_OFI_375
Length: 6ft; DCC: D2100753: SUS_OFI_228, SUS_OFI_229, SUS_OFI_274, SUS_OFI_275
Length: 6ft; DCC: D2100755: SUS_OFI_230, SUS_OFI_231
Length: 6ft; DCC: D1003058: SUS_OFI_117, SUS_OFI_119
Length: 6ft; DCC: D1003057: SUS_OFI_118, SUS_OFI_120
Length: 5ft; DCC: Connector J1(E): VAC_ZM6_001E
Length: 22FT; DCC: D2000456: VAC_ZM6_002

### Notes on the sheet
- OFI TOP
- (near C3) Re-use cables from old OFI cables.
- (near C6) See D1101917 for Flange Assignments
- OFI Picomotors from D3-F5 to D3-F11
- Need to ask if we can move
- (near C8) New in Vacuum cables.
- (near C4) and have OFI feedthroughs together. D3-F5 and D3-F6.
- Old OMC from HAM6
- ZM6-M1
- Re-use cables from O4 ZM6
- LLO
- 4 Floor Cable Bracket
- CB-3 2nd Floor
- D1001346-3
- HRTS
- LO3

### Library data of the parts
C1 C7 = CD OMC D1100304: System: SUS; Serial: Sxxxxxxx
C2 = BOSEM_OFI_M1: BOSEM; Serial: Sxxxxxxx; System: SUS; Rack: R?; Slot: U?
C3 C8 C13 = Flange: as C29 on sheet D2300380-v1_HAM5_SR3
C4 C9 = Satellite Amplifier UK D0900900: System: SUS; Serial: Sxxxxxxx
C5 = D1001346-4 4th Cable Bracket: Serial: Sxxxxxxx; System: SUS
C6 C11 C15 C21 C27 = VacFeedD25: as C32 on sheet D2300380-v1_HAM5_SR3
C10 = D1001346-4 3rd Cable Bracket: Serial: Sxxxxxxx; System: SUS
C12 = 4-BOSEM Array: as C39 on sheet D2300380-v1_HAM5_SR3
C14 = 3 Floor Cable Bracket 1st: Cable Bracket; Serial: Sxxxxxxx; System: SUS
C16 = 8 Channel Sat. Amp.: Serial: Sxxxxxxx; System: ISC
C17 = HAM A Coildriver: Serial: Sxxxxxxx; System: ISC
C18 = BOSEM_BS_M1: BOSEM; Serial: Sxxxxxxx; System: SUS; Rack: R?; Slot: U?
C19 = D1000234 D25 Quadrapus: Slot: U?; Rack: R?; Serial: Sxxxxxxx; System: SUS
C20 = D2000492-2 2nd Cable Bracket: D2000492-2 2/2 Cable Bracket for BSC Tables; Serial: Sxxxxxxx; System: SUS
C22 = Satellite Amplifier US D1002818: Serial: Sxxxxxxx
C23 C24 = CD HAM-A D1100687: Serial: Sxxxxxxx; System: ISC
C25 = D2100050 D25 2-udB9: Rack: SUS-R?; Serial: Sxxxxxxx; Slot: U?; System: SUS
C26 = D2000492-2 1st Cable Bracket: D2000492-2 1/2 Cable Bracket for BSC Tables; Serial: Sxxxxxxx; System: SUS

## Sheet D2300380-v1_SUSH56_ADC_DAC.SchDoc: SUS HAM5 Controls IO Chains
size C; Engineer: L. Sanchez; Organization: LIGO Laboratory; Address1: California Institute of Technology; Address2: Massachusetts Institute of Technology; DocumentNumber: D2300380; Revision: v1; SheetNumber: 4; SheetTotal: 7
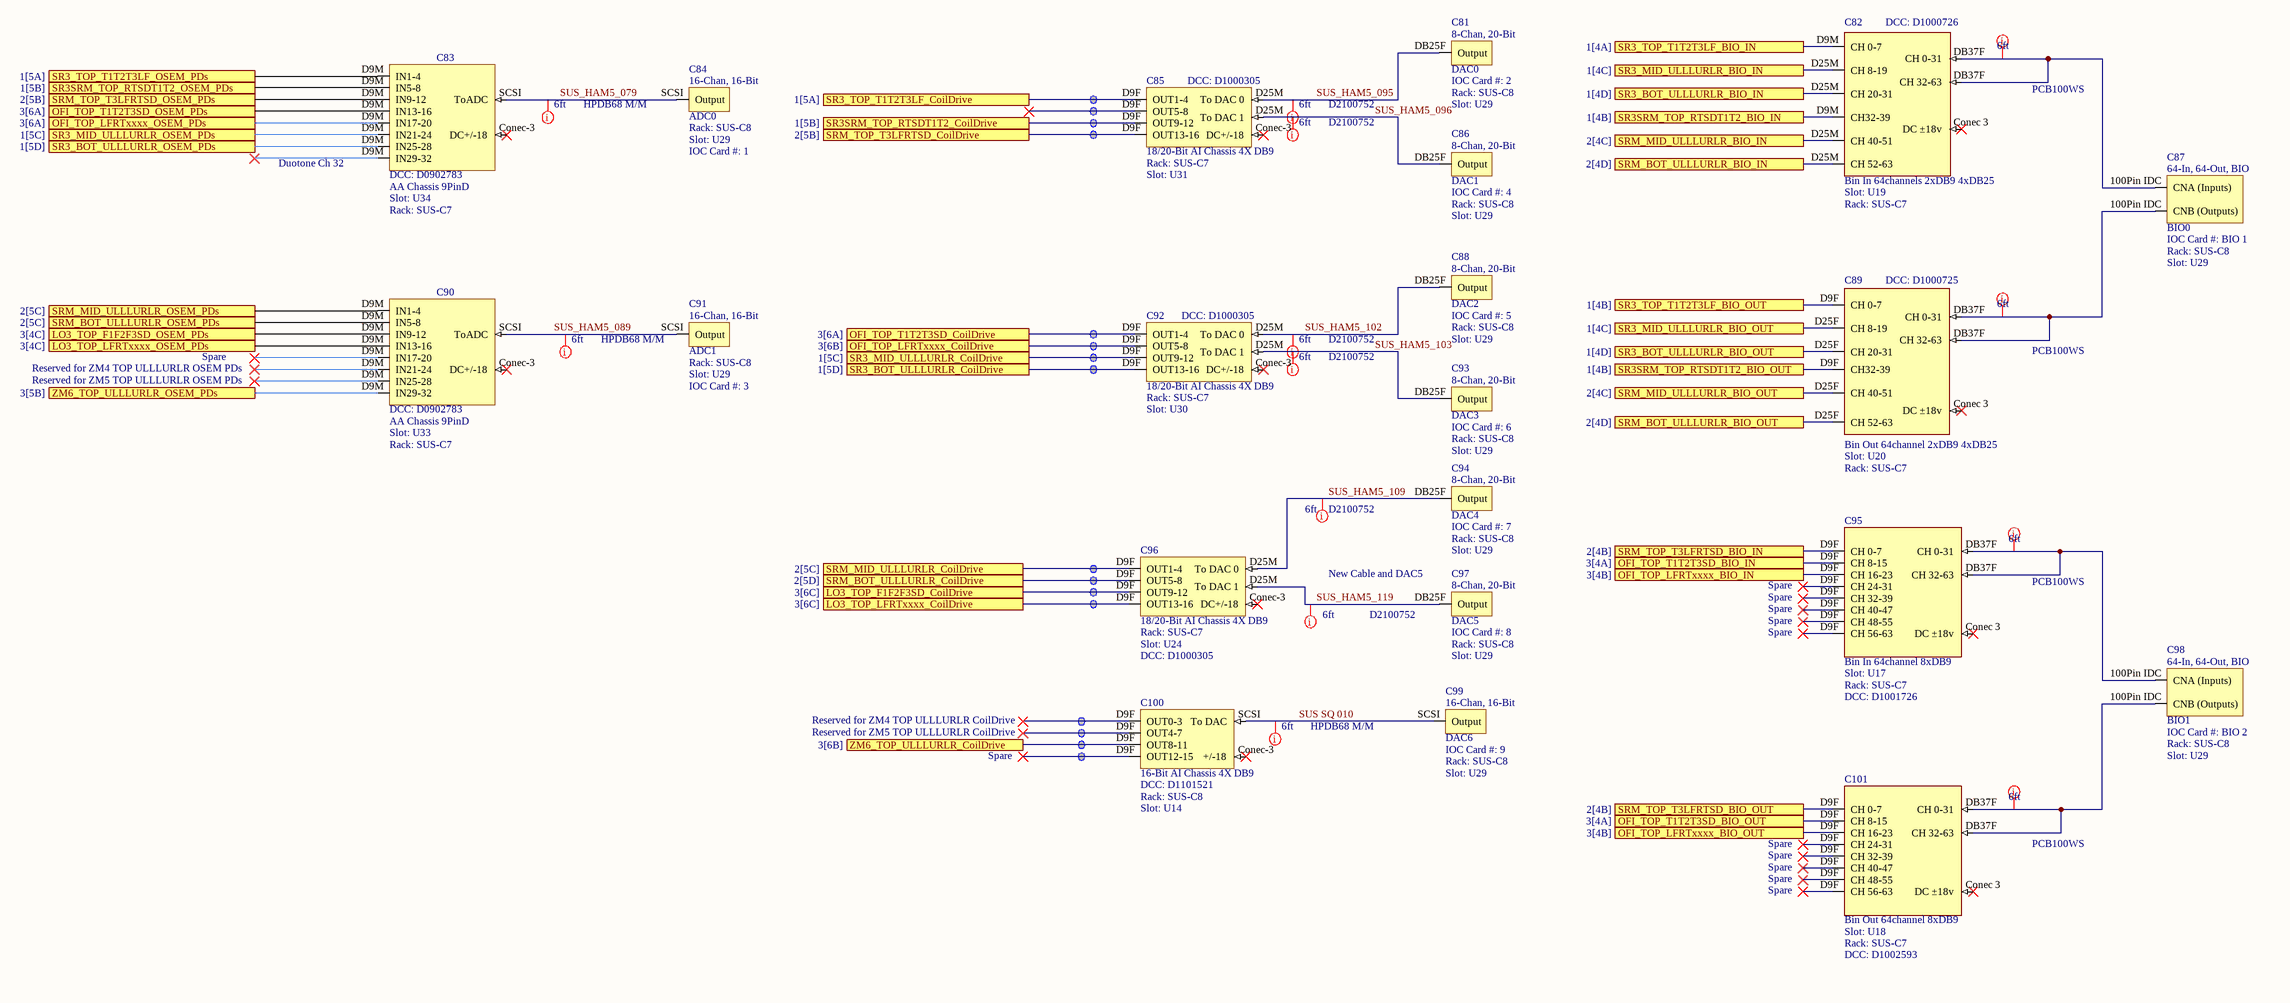
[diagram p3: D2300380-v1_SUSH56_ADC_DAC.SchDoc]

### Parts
C81  DAC0  IOC Card #: 2  Rack: SUS-C8  Slot: U29
C82  Bin In 64channels 2xDB9 4xDB25  Slot: U19  Rack: SUS-C7  DCC: D1000726
C83  AA Chassis 9PinD  DCC: D0902783  Rack: SUS-C7  Slot: U34
C84  ADC0  Rack: SUS-C8  Slot: U29  IOC Card #: 1
C85  18/20-Bit AI Chassis 4X DB9  Rack: SUS-C7  Slot: U31  DCC: D1000305
C86  DAC1  IOC Card #: 4  Rack: SUS-C8  Slot: U29
C87  BIO0  IOC Card #: BIO 1  Rack: SUS-C8  Slot: U29
C88  DAC2  IOC Card #: 5  Rack: SUS-C8  Slot: U29
C89  Bin Out 64channel 2xDB9 4xDB25  Slot: U20  Rack: SUS-C7  DCC: D1000725
C90  AA Chassis 9PinD  DCC: D0902783  Rack: SUS-C7  Slot: U33
C91  ADC1  Rack: SUS-C8  Slot: U29  IOC Card #: 3
C92  18/20-Bit AI Chassis 4X DB9  Rack: SUS-C7  Slot: U30  DCC: D1000305
C93  DAC3  IOC Card #: 6  Rack: SUS-C8  Slot: U29
C94  DAC4  IOC Card #: 7  Rack: SUS-C8  Slot: U29
C95  Bin In 64channel 8xDB9  Slot: U17  Rack: SUS-C7  DCC: D1001726
C96  18/20-Bit AI Chassis 4X DB9  Rack: SUS-C7  Slot: U24  DCC: D1000305
C97  DAC5  IOC Card #: 8  Rack: SUS-C8  Slot: U29
C98  BIO1  IOC Card #: BIO 2  Rack: SUS-C8  Slot: U29
C99  DAC6  IOC Card #: 9  Rack: SUS-C8  Slot: U29
C100  16-Bit AI Chassis 4X DB9  DCC: D1101521  Rack: SUS-C8  Slot: U14
C101  Bin Out 64channel 8xDB9  Slot: U18  Rack: SUS-C7  DCC: D1002593

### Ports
LO3_TOP_F1F2F3SD_CoilDrive (see 3[6C]), LO3_TOP_F1F2F3SD_OSEM_PDs (see 3[4C]), LO3_TOP_LFRTxxxx_CoilDrive (see 3[6C]), LO3_TOP_LFRTxxxx_OSEM_PDs (see 3[4C]), OFI_TOP_LFRTxxxx_BIO_IN (see 3[4B]), OFI_TOP_LFRTxxxx_BIO_OUT (see 3[4B]), OFI_TOP_LFRTxxxx_CoilDrive (see 3[6B]), OFI_TOP_LFRTxxxx_OSEM_PDs (see 3[6A]), OFI_TOP_T1T2T3SD_BIO_IN (see 3[4A]), OFI_TOP_T1T2T3SD_BIO_OUT (see 3[4A]), OFI_TOP_T1T2T3SD_CoilDrive (see 3[6A]), OFI_TOP_T1T2T3SD_OSEM_PDs (see 3[6A]), SR3_BOT_ULLLURLR_BIO_IN (see 1[4D]), SR3_BOT_ULLLURLR_BIO_OUT (see 1[4D]), SR3_BOT_ULLLURLR_CoilDrive (see 1[5D]), SR3_BOT_ULLLURLR_OSEM_PDs (see 1[5D]), SR3_MID_ULLLURLR_BIO_IN (see 1[4C]), SR3_MID_ULLLURLR_BIO_OUT (see 1[4C]), SR3_MID_ULLLURLR_CoilDrive (see 1[5C]), SR3_MID_ULLLURLR_OSEM_PDs (see 1[5C]), SR3_TOP_T1T2T3LF_BIO_IN (see 1[4A]), SR3_TOP_T1T2T3LF_BIO_OUT (see 1[4B]), SR3_TOP_T1T2T3LF_CoilDrive (see 1[5A]), SR3_TOP_T1T2T3LF_OSEM_PDs (see 1[5A]), SR3SRM_TOP_RTSDT1T2_BIO_IN (see 1[4B]), SR3SRM_TOP_RTSDT1T2_BIO_OUT (see 1[4B]), SR3SRM_TOP_RTSDT1T2_CoilDrive (see 1[5B]), SR3SRM_TOP_RTSDT1T2_OSEM_PDs (see 1[5B]), SRM_BOT_ULLLURLR_BIO_IN (see 2[4D]), SRM_BOT_ULLLURLR_BIO_OUT (see 2[4D]), SRM_BOT_ULLLURLR_CoilDrive (see 2[5D]), SRM_BOT_ULLLURLR_OSEM_PDs (see 2[5C]), SRM_MID_ULLLURLR_BIO_IN (see 2[4C]), SRM_MID_ULLLURLR_BIO_OUT (see 2[4C]), SRM_MID_ULLLURLR_CoilDrive (see 2[5C]), SRM_MID_ULLLURLR_OSEM_PDs (see 2[5C]), SRM_TOP_T3LFRTSD_BIO_IN (see 2[4B]), SRM_TOP_T3LFRTSD_BIO_OUT (see 2[4B]), SRM_TOP_T3LFRTSD_CoilDrive (see 2[5B]), SRM_TOP_T3LFRTSD_OSEM_PDs (see 2[5B]), ZM6_TOP_ULLLURLR_CoilDrive (see 3[6B]), ZM6_TOP_ULLLURLR_OSEM_PDs (see 3[5B])

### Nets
SUS SQ 010: C99.SCSI(Output) C100.SCSI(To_DAC)
SUS_HAM5_043: C82.D9M(CH_0-7) ; port SR3_TOP_T1T2T3LF_BIO_IN
SUS_HAM5_044: C89.D9F(CH_0-7) ; port SR3_TOP_T1T2T3LF_BIO_OUT
SUS_HAM5_045: C82.D9M(CH32-39) ; port SR3SRM_TOP_RTSDT1T2_BIO_IN
SUS_HAM5_046: C89.D9F(CH32-39) ; port SR3SRM_TOP_RTSDT1T2_BIO_OUT
SUS_HAM5_047: C95.D9F(CH_0-7) ; port SRM_TOP_T3LFRTSD_BIO_IN
SUS_HAM5_048: C101.D9F(CH_0-7) ; port SRM_TOP_T3LFRTSD_BIO_OUT
SUS_HAM5_055: C82.D25M(CH_8-19) ; port SR3_MID_ULLLURLR_BIO_IN
SUS_HAM5_056: C89.D25F(CH_8-19) ; port SR3_MID_ULLLURLR_BIO_OUT
SUS_HAM5_057: C82.D25M(CH_20-31) ; port SR3_BOT_ULLLURLR_BIO_IN
SUS_HAM5_058: C89.D25F(CH_20-31) ; port SR3_BOT_ULLLURLR_BIO_OUT
SUS_HAM5_059: C82.D25M(CH_40-51) ; port SRM_MID_ULLLURLR_BIO_IN
SUS_HAM5_060: C89.D25F(CH_40-51) ; port SRM_MID_ULLLURLR_BIO_OUT
SUS_HAM5_061: C82.D25M(CH_52-63) ; port SRM_BOT_ULLLURLR_BIO_IN
SUS_HAM5_062: C89.D25F(CH_52-63) ; port SRM_BOT_ULLLURLR_BIO_OUT
SUS_HAM5_071: C83.D9M(IN1-4) ; port SR3_TOP_T1T2T3LF_OSEM_PDs
SUS_HAM5_072: C83.D9M(IN5-8) ; port SR3SRM_TOP_RTSDT1T2_OSEM_PDs
SUS_HAM5_073: C83.D9M(IN9-12) ; port SRM_TOP_T3LFRTSD_OSEM_PDs
SUS_HAM5_077: C83.D9M(IN21-24) ; port SR3_MID_ULLLURLR_OSEM_PDs
SUS_HAM5_079: C83.SCSI(ToADC) C84.SCSI(Output)
SUS_HAM5_081: C83.D9M(IN25-28) ; port SR3_BOT_ULLLURLR_OSEM_PDs
SUS_HAM5_082: C90.D9M(IN1-4) ; port SRM_MID_ULLLURLR_OSEM_PDs
SUS_HAM5_083: C90.D9M(IN5-8) ; port SRM_BOT_ULLLURLR_OSEM_PDs
SUS_HAM5_089: C90.SCSI(ToADC) C91.SCSI(Output)
SUS_HAM5_091: C85.D9F(OUT1-4) ; port SR3_TOP_T1T2T3LF_CoilDrive
SUS_HAM5_092: C85.D9F(OUT9-12) ; port SR3SRM_TOP_RTSDT1T2_CoilDrive
SUS_HAM5_093: C85.D9F(OUT13-16) ; port SRM_TOP_T3LFRTSD_CoilDrive
SUS_HAM5_095: C81.DB25F(Output) C85.D25M(To_DAC_0)
SUS_HAM5_096: C85.D25M(To_DAC_1) C86.DB25F(Output)
SUS_HAM5_100: C92.D9F(OUT9-12) ; port SR3_MID_ULLLURLR_CoilDrive
SUS_HAM5_101: C92.D9F(OUT13-16) ; port SR3_BOT_ULLLURLR_CoilDrive
SUS_HAM5_102: C88.DB25F(Output) C92.D25M(To_DAC_0)
SUS_HAM5_103: C92.D25M(To_DAC_1) C93.DB25F(Output)
SUS_HAM5_105: C96.D9F(OUT1-4) ; port SRM_MID_ULLLURLR_CoilDrive
SUS_HAM5_106: C96.D9F(OUT5-8) ; port SRM_BOT_ULLLURLR_CoilDrive
SUS_HAM5_109: C94.DB25F(Output) C96.D25M(To_DAC_0)
SUS_HAM5_119: C96.D25M(To_DAC_1) C97.DB25F(Output)
SUS_LO3_004: C90.D9M(IN9-12) ; port LO3_TOP_F1F2F3SD_OSEM_PDs
SUS_LO3_006: C90.D9M(IN13-16) ; port LO3_TOP_LFRTxxxx_OSEM_PDs
SUS_LO3_007: C96.D9F(OUT9-12) ; port LO3_TOP_F1F2F3SD_CoilDrive
SUS_LO3_009: C96.D9F(OUT13-16) ; port LO3_TOP_LFRTxxxx_CoilDrive
SUS_OFI_117: C95.D9F(CH_8-15) ; port OFI_TOP_T1T2T3SD_BIO_IN
SUS_OFI_118: C101.D9F(CH_8-15) ; port OFI_TOP_T1T2T3SD_BIO_OUT
SUS_OFI_119: C95.D9F(CH_16-23) ; port OFI_TOP_LFRTxxxx_BIO_IN
SUS_OFI_120: C101.D9F(CH_16-23) ; port OFI_TOP_LFRTxxxx_BIO_OUT
SUS_OFI_274: C83.D9M(IN13-16) ; port OFI_TOP_T1T2T3SD_OSEM_PDs
SUS_OFI_275: C83.D9M(IN17-20) ; port OFI_TOP_LFRTxxxx_OSEM_PDs
SUS_OFI_374: C92.D9F(OUT1-4) ; port OFI_TOP_T1T2T3SD_CoilDrive
SUS_OFI_375: C92.D9F(OUT5-8) ; port OFI_TOP_LFRTxxxx_CoilDrive
SUS_ZM6_25: C90.D9M(IN29-32) ; port ZM6_TOP_ULLLURLR_OSEM_PDs
SUS_ZM6_28: C100.D9F(OUT0-3) ; port ZM6_TOP_ULLLURLR_CoilDrive
NetC82_DB37F: C82.DB37F(CH_0-31) C87.100Pin_IDC(CNA_(Inputs))
NetC87_100Pin IDC: C87.100Pin_IDC(CNB_(Outputs)) C89.DB37F(CH_0-31)
NetC95_DB37F: C95.DB37F(CH_0-31) C98.100Pin_IDC(CNA_(Inputs))
NetC98_100Pin IDC: C98.100Pin_IDC(CNB_(Outputs)) C101.DB37F(CH_0-31)

Not connected (* = marked no-connect by the designer): C82 Conec 3(DC_±18v)*; C83 Conec-3(DC+/-18)*; C85 Conec-3(DC+/-18)*; C89 Conec 3(DC_±18v)*; C90 Conec-3(DC+/-18)*; C92 Conec-3(DC+/-18)*; C95 Conec 3(DC_±18v)*; C96 Conec-3(DC+/-18)*; C100 Conec-3(+/-18)*; C101 Conec 3(DC_±18v)*

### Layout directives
Length: 6ft; DCC: Dxxxxxxx: NetC82_DB37F, NetC87_100Pin IDC, NetC95_DB37F, NetC98_100Pin IDC
Length: 6ft; DCC: HPDB68 M/M: SUS SQ 010, SUS_HAM5_079, SUS_HAM5_089
Length: 6ft; DCC: D2100752: SUS_HAM5_095, SUS_HAM5_096, SUS_HAM5_102, SUS_HAM5_103, SUS_HAM5_109, SUS_HAM5_119

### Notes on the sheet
- PCB100WS
- (near C83) Duotone Ch 32
- Reserved for ZM4 TOP ULLLURLR OSEM PDs
- Reserved for ZM5 TOP ULLLURLR OSEM PDs
- Spare
- (near C97) New Cable and DAC5
- Reserved for ZM4 TOP ULLLURLR CoilDrive
- Reserved for ZM5 TOP ULLLURLR CoilDrive

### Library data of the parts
C81 C86 C88 C93 C94 C97 = DAC-20: 8 Chan, 20 Bit DAC
C82 = Bin_In_64ch_2xDB9_4xDB25: Serial: Sxxxxxxx; System: SUS
C83 C90 = AA_9pinAll: ISC AA Chassis 9PinD; Serial: Sxxxxxxx
C84 C91 = ADC-16: 16 Chan, 16 Bit ADC
C85 C92 C96 = AI_9Pin_18_20_Bit: System: SUS; Serial: Sxxxxxxx
C87 C98 = Binary IO: 128 Chan, Contec DIO-6464L-PE
C89 = Bin_Out_64ch_2xDB9_4xDB25: Serial: Sxxxxxxx; System: SUS
C95 = Bin In 64cha_8xDB9: Serial: Sxxxxxxx; System: SUS
C99 = DAC-16: 16 Chan, 16 Bit DAC
C100 = AI_9pin_16_bit: AI Chassis 4X DB9 16-bit; Serial: Sxxxxxxx; System: ISC
C101 = Bin Out 64cha_8xDB9: Serial: Sxxxxxxx; System: SUS

## Sheet D2300380-v1_SUSAUXH56_ADC_DAC.SchDoc: SUS AUX HAM5 Coil Mon. IO Chains
size B; Engineer: L. Sanchez; Organization: LIGO Laboratory; Address1: California Institute of Technology; Address2: Massachusetts Institute of Technology; DocumentNumber: D2300380; Revision: v1; SheetNumber: 5; SheetTotal: 7
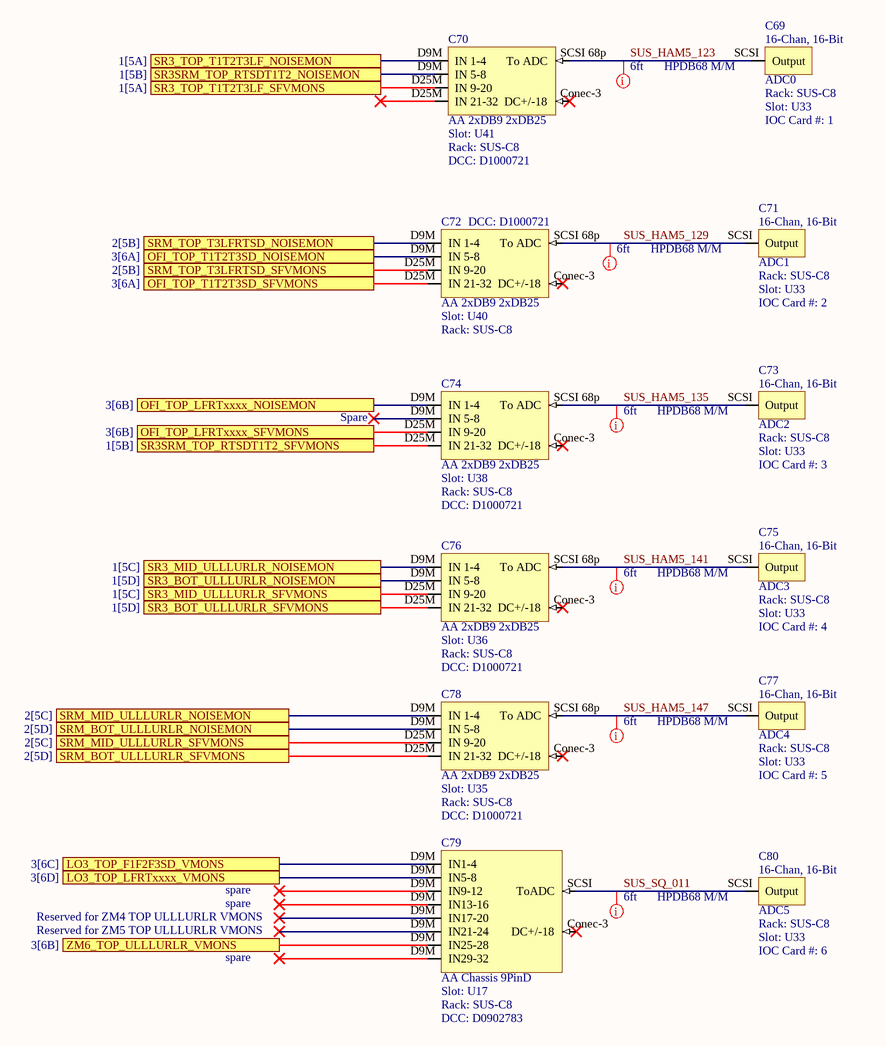
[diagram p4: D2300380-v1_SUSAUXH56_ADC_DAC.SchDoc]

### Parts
C69  ADC0  Rack: SUS-C8  Slot: U33  IOC Card #: 1
C70  AA 2xDB9 2xDB25  Slot: U41  Rack: SUS-C8  DCC: D1000721
C71  ADC1  Rack: SUS-C8  Slot: U33  IOC Card #: 2
C72  AA 2xDB9 2xDB25  Slot: U40  Rack: SUS-C8  DCC: D1000721
C73  ADC2  Rack: SUS-C8  Slot: U33  IOC Card #: 3
C74  AA 2xDB9 2xDB25  Slot: U38  Rack: SUS-C8  DCC: D1000721
C75  ADC3  Rack: SUS-C8  Slot: U33  IOC Card #: 4
C76  AA 2xDB9 2xDB25  Slot: U36  Rack: SUS-C8  DCC: D1000721
C77  ADC4  Rack: SUS-C8  Slot: U33  IOC Card #: 5
C78  AA 2xDB9 2xDB25  Slot: U35  Rack: SUS-C8  DCC: D1000721
C79  AA Chassis 9PinD  Slot: U17  Rack: SUS-C8  DCC: D0902783
C80  ADC5  Rack: SUS-C8  Slot: U33  IOC Card #: 6

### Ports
LO3_TOP_F1F2F3SD_VMONS (see 3[6C]), LO3_TOP_LFRTxxxx_VMONS (see 3[6D]), OFI_TOP_LFRTxxxx_NOISEMON (see 3[6B]), OFI_TOP_LFRTxxxx_SFVMONS (see 3[6B]), OFI_TOP_T1T2T3SD_NOISEMON (see 3[6A]), OFI_TOP_T1T2T3SD_SFVMONS (see 3[6A]), SR3_BOT_ULLLURLR_NOISEMON (see 1[5D]), SR3_BOT_ULLLURLR_SFVMONS (see 1[5D]), SR3_MID_ULLLURLR_NOISEMON (see 1[5C]), SR3_MID_ULLLURLR_SFVMONS (see 1[5C]), SR3_TOP_T1T2T3LF_NOISEMON (see 1[5A]), SR3_TOP_T1T2T3LF_SFVMONS (see 1[5A]), SR3SRM_TOP_RTSDT1T2_NOISEMON (see 1[5B]), SR3SRM_TOP_RTSDT1T2_SFVMONS (see 1[5B]), SRM_BOT_ULLLURLR_NOISEMON (see 2[5D]), SRM_BOT_ULLLURLR_SFVMONS (see 2[5D]), SRM_MID_ULLLURLR_NOISEMON (see 2[5C]), SRM_MID_ULLLURLR_SFVMONS (see 2[5C]), SRM_TOP_T3LFRTSD_NOISEMON (see 2[5B]), SRM_TOP_T3LFRTSD_SFVMONS (see 2[5B]), ZM6_TOP_ULLLURLR_VMONS (see 3[6B])

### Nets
SUS_HAM5_119: C70.D9M(IN_1-4) ; port SR3_TOP_T1T2T3LF_NOISEMON
SUS_HAM5_120: C70.D9M(IN_5-8) ; port SR3SRM_TOP_RTSDT1T2_NOISEMON
SUS_HAM5_121: C70.D25M(IN_9-20) ; port SR3_TOP_T1T2T3LF_SFVMONS
SUS_HAM5_122: C74.D25M(IN_21-32) ; port SR3SRM_TOP_RTSDT1T2_SFVMONS
SUS_HAM5_123: C69.SCSI(Output) C70.SCSI_68p(To_ADC)
SUS_HAM5_125: C72.D9M(IN_1-4) ; port SRM_TOP_T3LFRTSD_NOISEMON
SUS_HAM5_127: C72.D25M(IN_9-20) ; port SRM_TOP_T3LFRTSD_SFVMONS
SUS_HAM5_129: C71.SCSI(Output) C72.SCSI_68p(To_ADC)
SUS_HAM5_135: C73.SCSI(Output) C74.SCSI_68p(To_ADC)
SUS_HAM5_137: C76.D9M(IN_1-4) ; port SR3_MID_ULLLURLR_NOISEMON
SUS_HAM5_138: C76.D9M(IN_5-8) ; port SR3_BOT_ULLLURLR_NOISEMON
SUS_HAM5_139: C76.D25M(IN_9-20) ; port SR3_MID_ULLLURLR_SFVMONS
SUS_HAM5_140: C76.D25M(IN_21-32) ; port SR3_BOT_ULLLURLR_SFVMONS
SUS_HAM5_141: C75.SCSI(Output) C76.SCSI_68p(To_ADC)
SUS_HAM5_143: C78.D9M(IN_1-4) ; port SRM_MID_ULLLURLR_NOISEMON
SUS_HAM5_144: C78.D9M(IN_5-8) ; port SRM_BOT_ULLLURLR_NOISEMON
SUS_HAM5_145: C78.D25M(IN_9-20) ; port SRM_MID_ULLLURLR_SFVMONS
SUS_HAM5_146: C78.D25M(IN_21-32) ; port SRM_BOT_ULLLURLR_SFVMONS
SUS_HAM5_147: C77.SCSI(Output) C78.SCSI_68p(To_ADC)
SUS_LO3_008: C79.D9M(IN1-4) ; port LO3_TOP_F1F2F3SD_VMONS
SUS_LO3_010: C79.D9M(IN5-8) ; port LO3_TOP_LFRTxxxx_VMONS
SUS_OFI_228: C72.D9M(IN_5-8) ; port OFI_TOP_T1T2T3SD_NOISEMON
SUS_OFI_229: C74.D9M(IN_1-4) ; port OFI_TOP_LFRTxxxx_NOISEMON
SUS_OFI_230: C72.D25M(IN_21-32) ; port OFI_TOP_T1T2T3SD_SFVMONS
SUS_OFI_231: C74.D25M(IN_9-20) ; port OFI_TOP_LFRTxxxx_SFVMONS
SUS_SQ_011: C79.SCSI(ToADC) C80.SCSI(Output)
SUS_ZM6_29: C79.D9M(IN25-28) ; port ZM6_TOP_ULLLURLR_VMONS

Not connected (* = marked no-connect by the designer): C70 Conec-3(DC+/-18)*; C72 Conec-3(DC+/-18)*; C74 Conec-3(DC+/-18)*; C76 Conec-3(DC+/-18)*; C78 Conec-3(DC+/-18)*; C79 Conec-3(DC+/-18)*

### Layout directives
Length: 6ft; DCC: HPDB68 M/M: SUS_HAM5_123, SUS_HAM5_129, SUS_HAM5_135, SUS_HAM5_141, SUS_HAM5_147, SUS_SQ_011

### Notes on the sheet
- Spare
- Reserved for ZM4 TOP ULLLURLR VMONS
- Reserved for ZM5 TOP ULLLURLR VMONS
- spare

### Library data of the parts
C69 C71 C73 C75 C77 C80 = ADC-16: 16 Chan, 16 Bit ADC
C70 C72 C74 C76 C78 = AA 2xDB9M 2xDB25M: System: SUS; Serial: Sxxxxxxx
C79 = AA_9pinAll: ISC AA Chassis 9PinD; Serial: Sxxxxxxx

## Sheet D2300380-v1_RACK_SUS_R4.SchDoc: FIELD RACK SUS-R4
size C; Engineer: L. Sanchez; Organization: LIGO Laboratory; Address1: California Institute of Technology; Address2: Massachusetts Institute of Technology; DocumentNumber: D2300380; Revision: v1; SheetNumber: 6; SheetTotal: 7
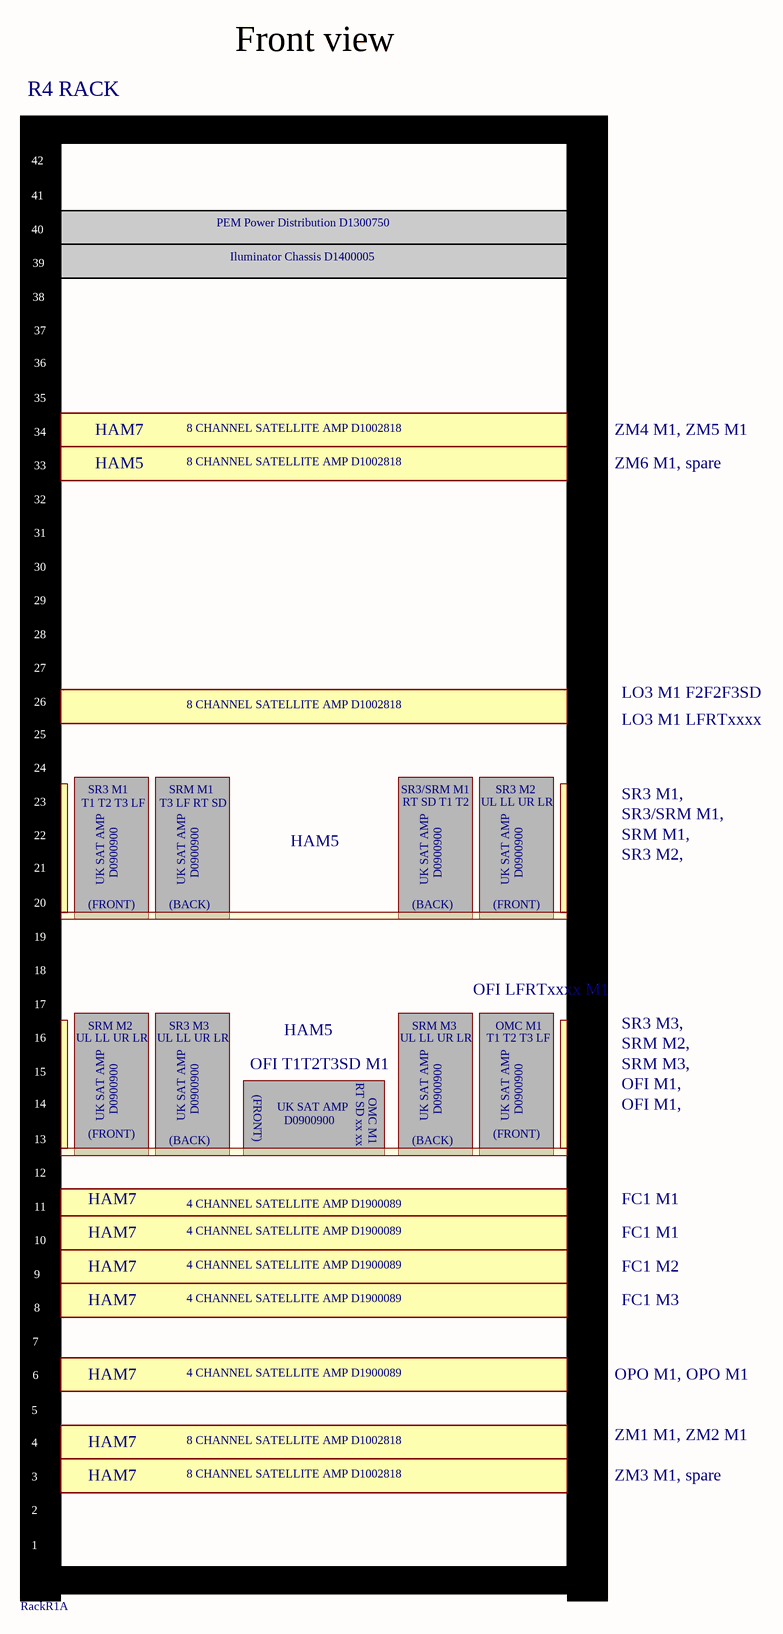
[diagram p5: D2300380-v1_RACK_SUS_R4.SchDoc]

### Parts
RackR1  1U  Rack 42 pos  (value not drawn)  (part A of 2)

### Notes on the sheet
- Front view
- R4 RACK
- PEM Power Distribution D1300750
- Iluminator Chassis D1400005
- HAM7
- HAM5
- 8 CHANNEL SATELLITE AMP D1002818
- ZM4 M1, ZM5 M1
- ZM6 M1, spare
- LO3 M1 F2F2F3SD
- LO3 M1 LFRTxxxx
- T1 T2 T3 LF
- SR3 M1
- T3 LF RT SD
- SRM M1
- SR3/SRM M1
- RT SD T1 T2
- UL LL UR LR
- SR3 M2
- SR3 M1,
- SR3/SRM M1,
- UK SAT AMP
- D0900900
- SRM M1,
- SR3 M2,
- (FRONT)
- (BACK)
- OFI LFRTxxxx M1
- SRM M2
- SR3 M3
- OFI T1T2T3SD M1
- RT SD xx xx
- SRM M3
- OMC M1
- SR3 M3,
- SRM M2,
- SRM M3,
- OFI M1,
- 4 CHANNEL SATELLITE AMP D1900089
- FC1 M1
- FC1 M2
- FC1 M3
- OPO M1, OPO M1
- ZM1 M1, ZM2 M1
- ZM3 M1, spare

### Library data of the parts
RackR1 = RACK_42

## Sheet D2300380-v2_RACK_SUS_C7_C8.SchDoc: REMOTE RACK SUS-C7 & SUS-C8
size C; Engineer: L. Sanchez; Organization: LIGO Laboratory; Address1: California Institute of Technology; Address2: Massachusetts Institute of Technology; DocumentNumber: D2300380; Revision: v1; SheetNumber: 7; SheetTotal: 7
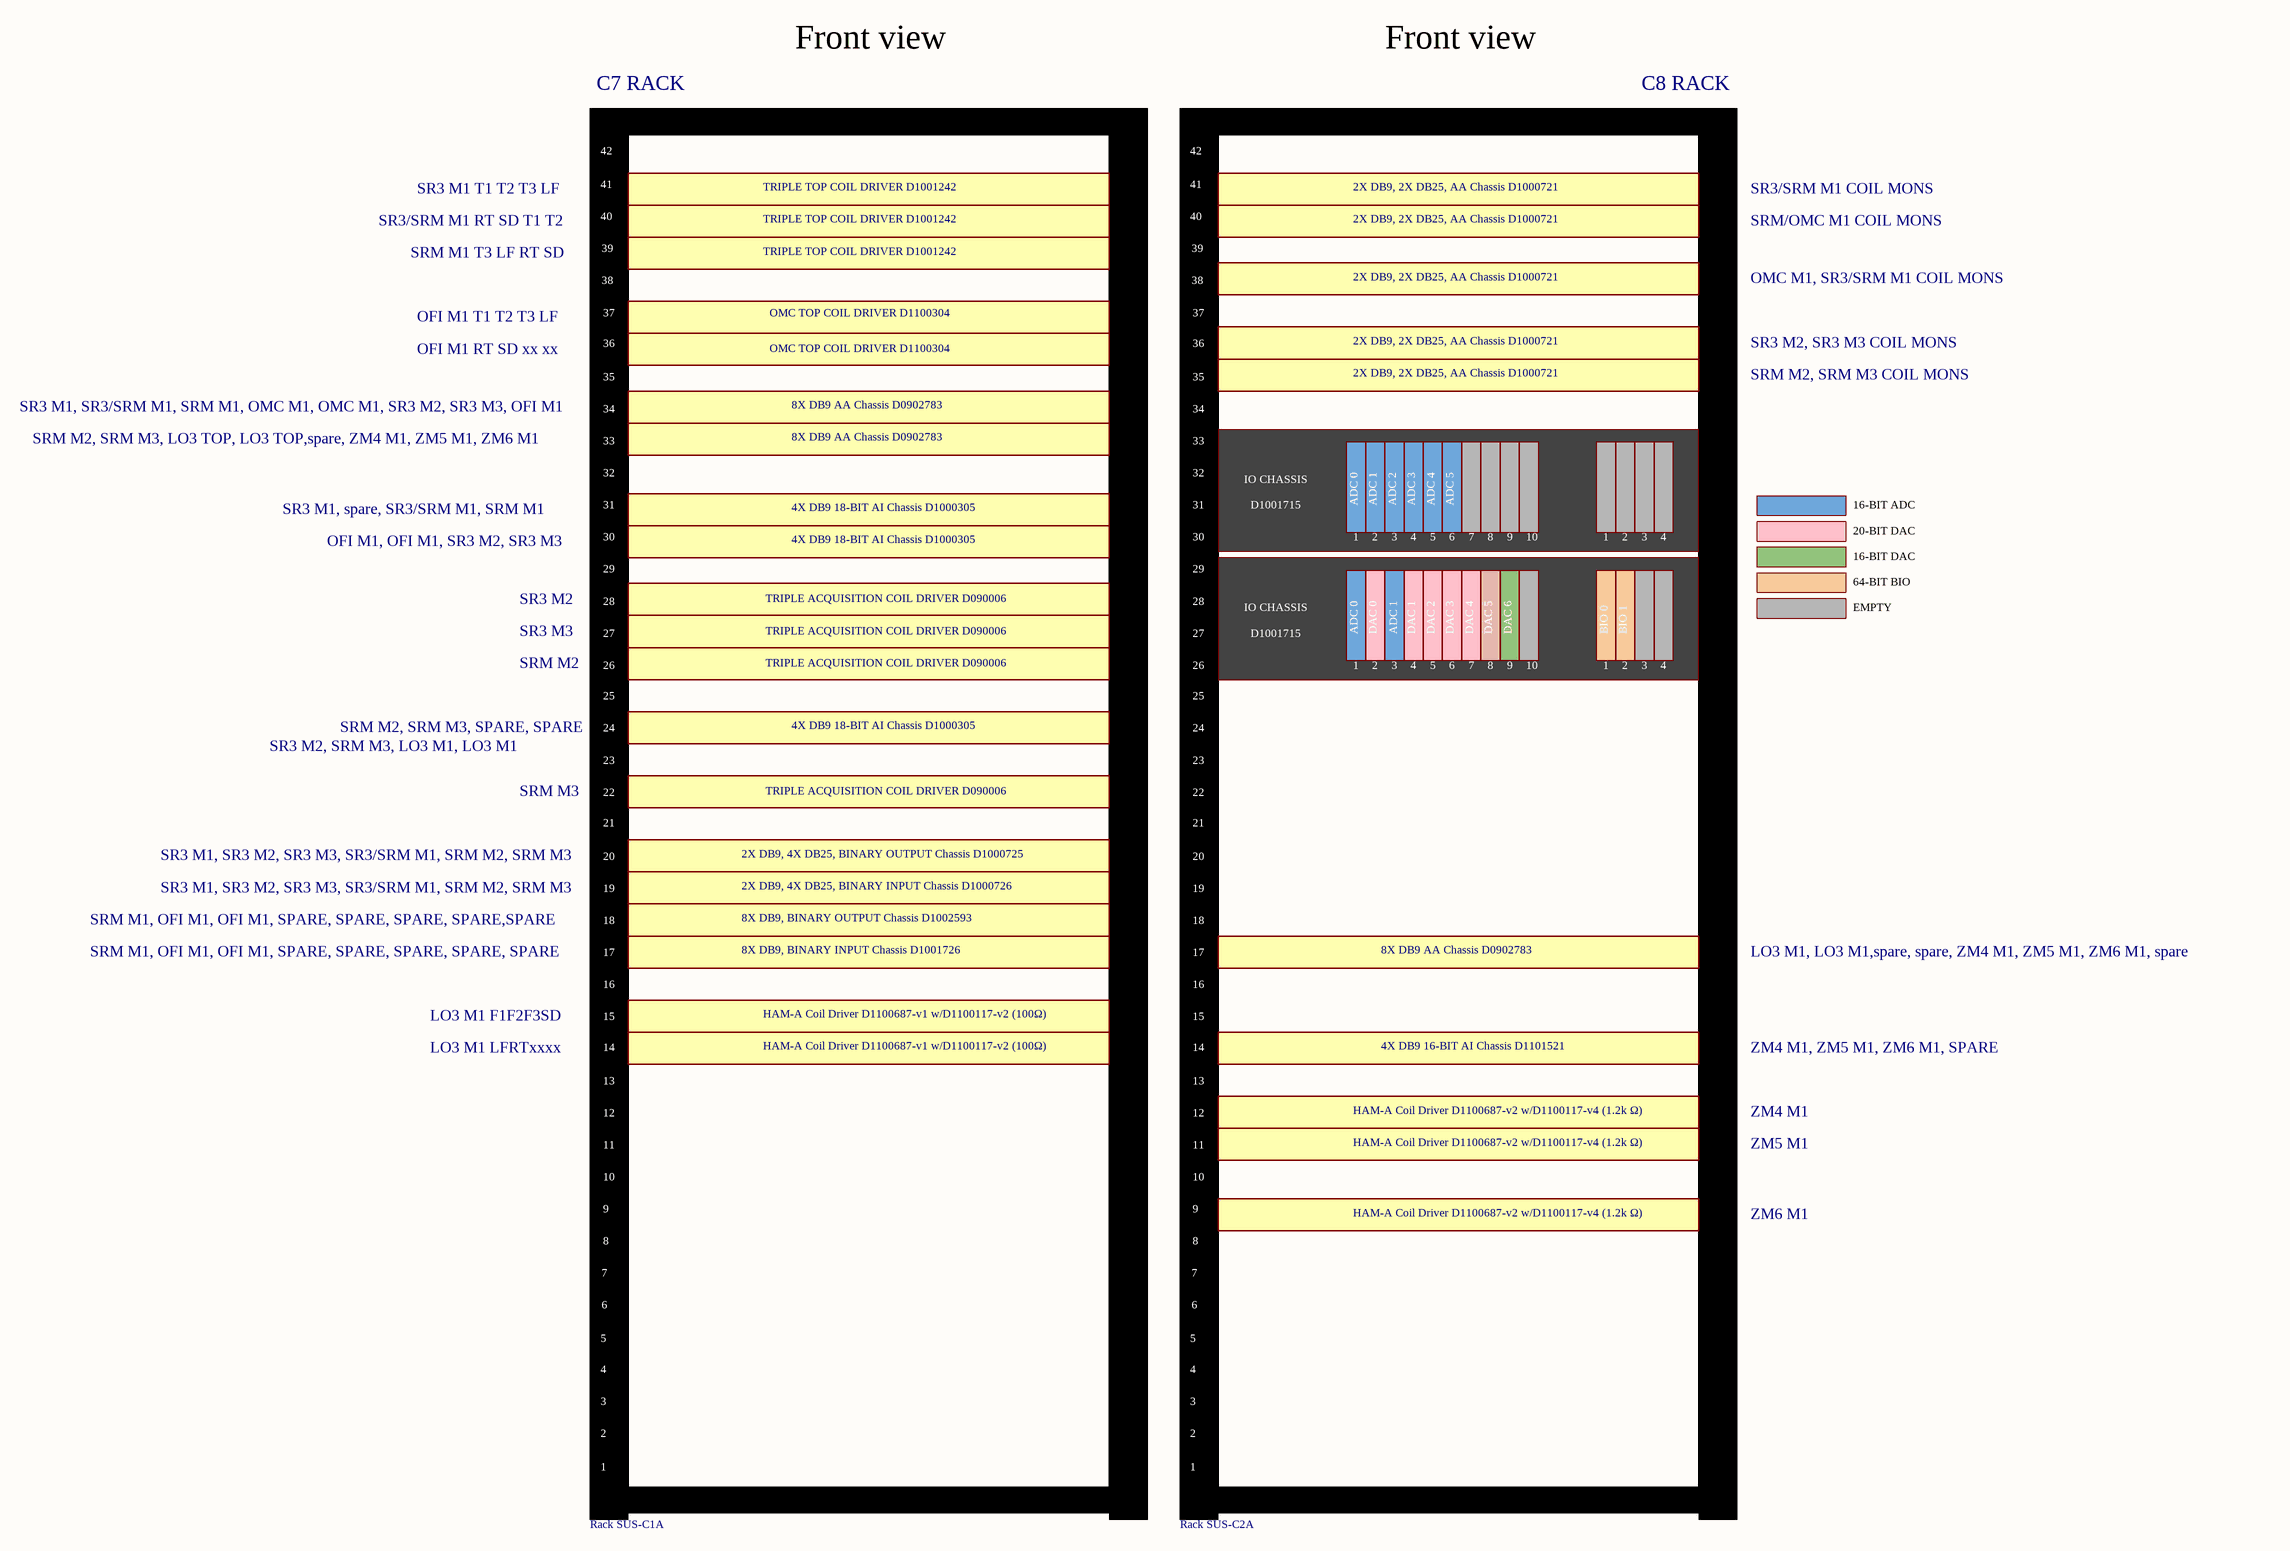
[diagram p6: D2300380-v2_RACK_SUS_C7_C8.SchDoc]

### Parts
Rack_SUS-C1  1U  Rack 42 pos  (value not drawn)  (part A of 2)
Rack_SUS-C2  1U  Rack 42 pos  (value not drawn)  (part A of 2)

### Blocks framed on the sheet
2X DB9, 4X DB25, BINARY OUTPUT Chassis D1000725: Rack_SUS-C1

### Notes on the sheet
- Front view
- C7 RACK
- C8 RACK
- SR3 M1 T1 T2 T3 LF
- TRIPLE TOP COIL DRIVER D1001242
- 2X DB9, 2X DB25, AA Chassis D1000721
- SR3/SRM M1 COIL MONS
- SR3/SRM M1 RT SD T1 T2
- SRM M1 T3 LF RT SD
- SRM/OMC M1 COIL MONS
- OFI M1 T1 T2 T3 LF
- OMC TOP COIL DRIVER D1100304
- OMC M1, SR3/SRM M1 COIL MONS
- OFI M1 RT SD xx xx
- SR3 M2, SR3 M3 COIL MONS
- SRM M2, SRM M3 COIL MONS
- SR3 M1, SR3/SRM M1, SRM M1, OMC M1, OMC M1, SR3 M2, SR3 M3, OFI M1
- SRM M2, SRM M3, LO3 TOP, LO3 TOP,spare, ZM4 M1, ZM5 M1, ZM6 M1
- 8X DB9 AA Chassis D0902783
- SR3 M1, spare, SR3/SRM M1, SRM M1
- 4X DB9 18-BIT AI Chassis D1000305
- IO CHASSIS
- D1001715
- ADC 0
- ADC 1
- ADC 2
- ADC 3
- ADC 4
- ADC 5
- 16-BIT ADC
- OFI M1, OFI M1, SR3 M2, SR3 M3
- 1
- 2
- 3
- 4
- 5
- 6
- 7
- 8
- 9
- 10
- 20-BIT DAC
- 16-BIT DAC
- 64-BIT BIO
- SR3 M2
- SR3 M3
- TRIPLE ACQUISITION COIL DRIVER D090006
- DAC 0
- DAC 1
- DAC 2
- DAC 3
- DAC 4
- DAC 5
- DAC 6
- BIO 0
- BIO 1
- EMPTY
- SRM M2
- SR3 M2, SRM M3, LO3 M1, LO3 M1
- SRM M2, SRM M3, SPARE, SPARE
- SRM M3
- SR3 M1, SR3 M2, SR3 M3, SR3/SRM M1, SRM M2, SRM M3
- (near Rack_SUS-C1) 2X DB9, 4X DB25, BINARY INPUT Chassis D1000726
- SRM M1, OFI M1, OFI M1, SPARE, SPARE, SPARE, SPARE,SPARE
- SRM M1, OFI M1, OFI M1, SPARE, SPARE, SPARE, SPARE, SPARE
- 8X DB9, BINARY OUTPUT Chassis D1002593
- 8X DB9, BINARY INPUT Chassis D1001726
- LO3 M1, LO3 M1,spare, spare, ZM4 M1, ZM5 M1, ZM6 M1, spare
- LO3 M1 F1F2F3SD
- HAM-A Coil Driver D1100687-v1 w/D1100117-v2 (100Ω)
- LO3 M1 LFRTxxxx
- 4X DB9 16-BIT AI Chassis D1101521
- ZM4 M1, ZM5 M1, ZM6 M1, SPARE
- HAM-A Coil Driver D1100687-v2 w/D1100117-v4 (1.2k Ω)
- ZM4 M1
- ZM5 M1
- ZM6 M1

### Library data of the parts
Rack_SUS-C1 Rack_SUS-C2 = RACK_42

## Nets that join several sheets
SUS_HAM5_043: D2300380-v1_HAM5_SR3 (C33.D37F), D2300380-v1_SUSH56_ADC_DAC (C82.D9M)
SUS_HAM5_044: D2300380-v1_HAM5_SR3 (C33.D37M), D2300380-v1_SUSH56_ADC_DAC (C89.D9F)
SUS_HAM5_045: D2300380-v1_HAM5_SR3 (C38.D37F), D2300380-v1_SUSH56_ADC_DAC (C82.D9M)
SUS_HAM5_046: D2300380-v1_HAM5_SR3 (C38.D37M), D2300380-v1_SUSH56_ADC_DAC (C89.D9F)
SUS_HAM5_047: D2300380-v1_HAM5_SRM (C56.D37F), D2300380-v1_SUSH56_ADC_DAC (C95.D9F)
SUS_HAM5_048: D2300380-v1_HAM5_SRM (C56.D37M), D2300380-v1_SUSH56_ADC_DAC (C101.D9F)
SUS_HAM5_055: D2300380-v1_HAM5_SR3 (C44.D25F), D2300380-v1_SUSH56_ADC_DAC (C82.D25M)
SUS_HAM5_056: D2300380-v1_HAM5_SR3 (C44.D25M), D2300380-v1_SUSH56_ADC_DAC (C89.D25F)
SUS_HAM5_057: D2300380-v1_HAM5_SR3 (C50.D25F), D2300380-v1_SUSH56_ADC_DAC (C82.D25M)
SUS_HAM5_058: D2300380-v1_HAM5_SR3 (C50.D25M), D2300380-v1_SUSH56_ADC_DAC (C89.D25F)
SUS_HAM5_059: D2300380-v1_HAM5_SRM (C62.D25F), D2300380-v1_SUSH56_ADC_DAC (C82.D25M)
SUS_HAM5_060: D2300380-v1_HAM5_SRM (C62.D25M), D2300380-v1_SUSH56_ADC_DAC (C89.D25F)
SUS_HAM5_061: D2300380-v1_HAM5_SRM (C68.D25F), D2300380-v1_SUSH56_ADC_DAC (C82.D25M)
SUS_HAM5_062: D2300380-v1_HAM5_SRM (C68.D25M), D2300380-v1_SUSH56_ADC_DAC (C89.D25F)
SUS_HAM5_071: D2300380-v1_HAM5_SR3 (C33.D9F), D2300380-v1_SUSH56_ADC_DAC (C83.D9M)
SUS_HAM5_072: D2300380-v1_HAM5_SR3 (C38.D9F), D2300380-v1_SUSH56_ADC_DAC (C83.D9M)
SUS_HAM5_073: D2300380-v1_HAM5_SRM (C56.D9F), D2300380-v1_SUSH56_ADC_DAC (C83.D9M)
SUS_HAM5_077: D2300380-v1_HAM5_SR3 (C44.D9F), D2300380-v1_SUSH56_ADC_DAC (C83.D9M)
SUS_HAM5_081: D2300380-v1_HAM5_SR3 (C50.D9F), D2300380-v1_SUSH56_ADC_DAC (C83.D9M)
SUS_HAM5_082: D2300380-v1_HAM5_SRM (C62.D9F), D2300380-v1_SUSH56_ADC_DAC (C90.D9M)
SUS_HAM5_083: D2300380-v1_HAM5_SRM (C68.D9F), D2300380-v1_SUSH56_ADC_DAC (C90.D9M)
SUS_HAM5_091: D2300380-v1_HAM5_SR3 (C33.D9M), D2300380-v1_SUSH56_ADC_DAC (C85.D9F)
SUS_HAM5_092: D2300380-v1_HAM5_SR3 (C38.D9M), D2300380-v1_SUSH56_ADC_DAC (C85.D9F)
SUS_HAM5_093: D2300380-v1_HAM5_SRM (C56.D9M), D2300380-v1_SUSH56_ADC_DAC (C85.D9F)
SUS_HAM5_100: D2300380-v1_HAM5_SR3 (C44.D9M), D2300380-v1_SUSH56_ADC_DAC (C92.D9F)
SUS_HAM5_101: D2300380-v1_HAM5_SR3 (C50.D9M), D2300380-v1_SUSH56_ADC_DAC (C92.D9F)
SUS_HAM5_105: D2300380-v1_HAM5_SRM (C62.D9M), D2300380-v1_SUSH56_ADC_DAC (C96.D9F)
SUS_HAM5_106: D2300380-v1_HAM5_SRM (C68.D9M), D2300380-v1_SUSH56_ADC_DAC (C96.D9F)
SUS_HAM5_119: D2300380-v1_HAM5_SR3 (C33.D9F), D2300380-v1_SUSAUXH56_ADC_DAC (C70.D9M)
SUS_HAM5_120: D2300380-v1_HAM5_SR3 (C38.D9F), D2300380-v1_SUSAUXH56_ADC_DAC (C70.D9M)
SUS_HAM5_121: D2300380-v1_HAM5_SR3 (C33.D25M), D2300380-v1_SUSAUXH56_ADC_DAC (C70.D25M)
SUS_HAM5_122: D2300380-v1_HAM5_SR3 (C38.D25M), D2300380-v1_SUSAUXH56_ADC_DAC (C74.D25M)
SUS_HAM5_125: D2300380-v1_HAM5_SRM (C56.D9F), D2300380-v1_SUSAUXH56_ADC_DAC (C72.D9M)
SUS_HAM5_127: D2300380-v1_HAM5_SRM (C56.D25M), D2300380-v1_SUSAUXH56_ADC_DAC (C72.D25M)
SUS_HAM5_137: D2300380-v1_HAM5_SR3 (C44.D9F), D2300380-v1_SUSAUXH56_ADC_DAC (C76.D9M)
SUS_HAM5_138: D2300380-v1_HAM5_SR3 (C50.D9F), D2300380-v1_SUSAUXH56_ADC_DAC (C76.D9M)
SUS_HAM5_139: D2300380-v1_HAM5_SR3 (C44.D25M), D2300380-v1_SUSAUXH56_ADC_DAC (C76.D25M)
SUS_HAM5_140: D2300380-v1_HAM5_SR3 (C50.D25M), D2300380-v1_SUSAUXH56_ADC_DAC (C76.D25M)
SUS_HAM5_143: D2300380-v1_HAM5_SRM (C62.D9F), D2300380-v1_SUSAUXH56_ADC_DAC (C78.D9M)
SUS_HAM5_144: D2300380-v1_HAM5_SRM (C68.D9F), D2300380-v1_SUSAUXH56_ADC_DAC (C78.D9M)
SUS_HAM5_145: D2300380-v1_HAM5_SRM (C62.D25M), D2300380-v1_SUSAUXH56_ADC_DAC (C78.D25M)
SUS_HAM5_146: D2300380-v1_HAM5_SRM (C68.D25M), D2300380-v1_SUSAUXH56_ADC_DAC (C78.D25M)
SUS_HAM5_151C: D2300380-v1_HAM5_SR3 (C34.MicroD9), D2300380-v1_HAM5_SRM (C51.D9F)
SUS_HAM5_151D: D2300380-v1_HAM5_SR3 (C34.MicroD9), D2300380-v1_HAM5_SRM (C51.D9F)
SUS_LO3_004: D2300380-v2_HAM5_OFI_ZM6_LO3 (C22.D9F), D2300380-v1_SUSH56_ADC_DAC (C90.D9M)
SUS_LO3_006: D2300380-v2_HAM5_OFI_ZM6_LO3 (C22.D9F), D2300380-v1_SUSH56_ADC_DAC (C90.D9M)
SUS_LO3_007: D2300380-v2_HAM5_OFI_ZM6_LO3 (C23.D9M), D2300380-v1_SUSH56_ADC_DAC (C96.D9F)
SUS_LO3_008: D2300380-v2_HAM5_OFI_ZM6_LO3 (C23.D9F), D2300380-v1_SUSAUXH56_ADC_DAC (C79.D9M)
SUS_LO3_009: D2300380-v2_HAM5_OFI_ZM6_LO3 (C24.D9M), D2300380-v1_SUSH56_ADC_DAC (C96.D9F)
SUS_LO3_010: D2300380-v2_HAM5_OFI_ZM6_LO3 (C24.D9F), D2300380-v1_SUSAUXH56_ADC_DAC (C79.D9M)
SUS_OFI_117: D2300380-v2_HAM5_OFI_ZM6_LO3 (C1.D37F), D2300380-v1_SUSH56_ADC_DAC (C95.D9F)
SUS_OFI_118: D2300380-v2_HAM5_OFI_ZM6_LO3 (C1.D37M), D2300380-v1_SUSH56_ADC_DAC (C101.D9F)
SUS_OFI_119: D2300380-v2_HAM5_OFI_ZM6_LO3 (C7.D37F), D2300380-v1_SUSH56_ADC_DAC (C95.D9F)
SUS_OFI_120: D2300380-v2_HAM5_OFI_ZM6_LO3 (C7.D37M), D2300380-v1_SUSH56_ADC_DAC (C101.D9F)
SUS_OFI_228: D2300380-v2_HAM5_OFI_ZM6_LO3 (C1.D9F), D2300380-v1_SUSAUXH56_ADC_DAC (C72.D9M)
SUS_OFI_229: D2300380-v2_HAM5_OFI_ZM6_LO3 (C7.D9F), D2300380-v1_SUSAUXH56_ADC_DAC (C74.D9M)
SUS_OFI_230: D2300380-v2_HAM5_OFI_ZM6_LO3 (C1.D25M), D2300380-v1_SUSAUXH56_ADC_DAC (C72.D25M)
SUS_OFI_231: D2300380-v2_HAM5_OFI_ZM6_LO3 (C7.D25M), D2300380-v1_SUSAUXH56_ADC_DAC (C74.D25M)
SUS_OFI_274: D2300380-v2_HAM5_OFI_ZM6_LO3 (C1.D9F), D2300380-v1_SUSH56_ADC_DAC (C83.D9M)
SUS_OFI_275: D2300380-v2_HAM5_OFI_ZM6_LO3 (C7.D9F), D2300380-v1_SUSH56_ADC_DAC (C83.D9M)
SUS_OFI_374: D2300380-v2_HAM5_OFI_ZM6_LO3 (C1.D9M), D2300380-v1_SUSH56_ADC_DAC (C92.D9F)
SUS_OFI_375: D2300380-v2_HAM5_OFI_ZM6_LO3 (C7.D9M), D2300380-v1_SUSH56_ADC_DAC (C92.D9F)
SUS_ZM6_25: D2300380-v2_HAM5_OFI_ZM6_LO3 (C16.D9F), D2300380-v1_SUSH56_ADC_DAC (C90.D9M)
SUS_ZM6_28: D2300380-v2_HAM5_OFI_ZM6_LO3 (C17.D9M), D2300380-v1_SUSH56_ADC_DAC (C100.D9F)
SUS_ZM6_29: D2300380-v2_HAM5_OFI_ZM6_LO3 (C17.D9F), D2300380-v1_SUSAUXH56_ADC_DAC (C79.D9M)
